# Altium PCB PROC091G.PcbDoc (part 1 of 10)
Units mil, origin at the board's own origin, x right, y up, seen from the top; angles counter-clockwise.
Board outline 4538.11 x 994.94 mil, 8 copper layers (Top Layer, GND1, Sig1, PWR1, PWR2, Sig2, GND2, Bottom Layer), stack 59.155 mil thick; 446 components, 329 nets, 5050 pads, 868 vias.
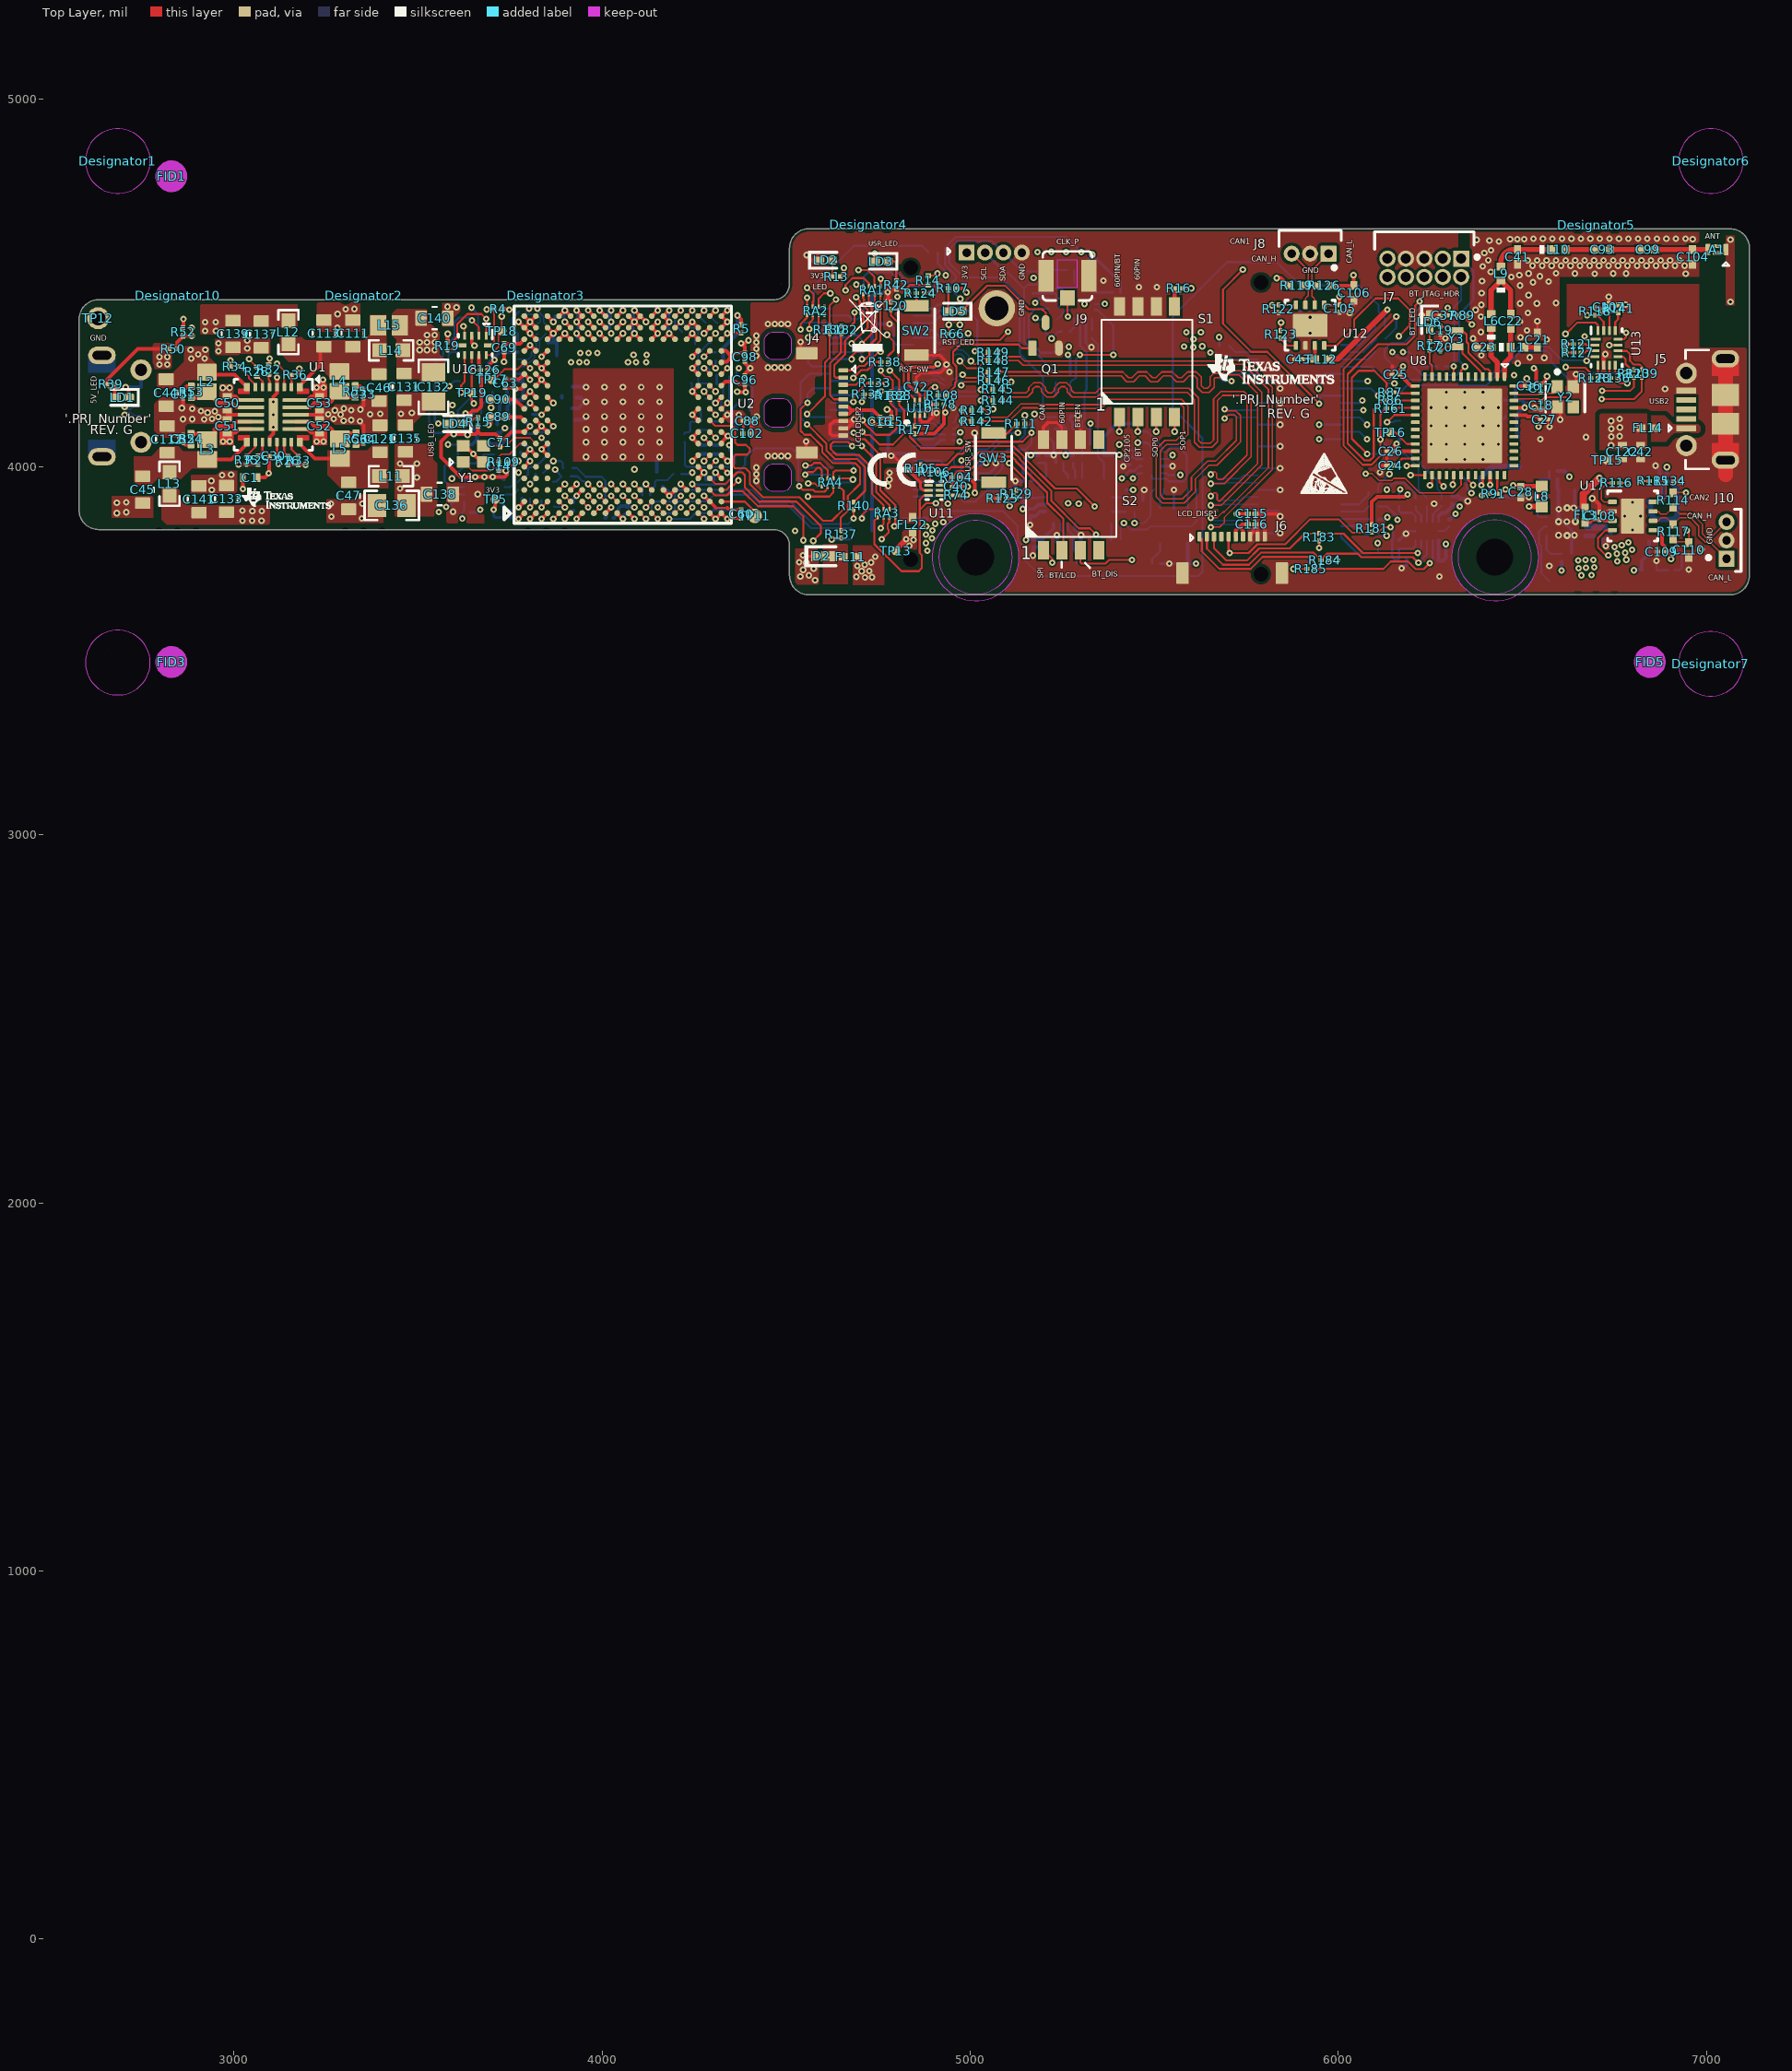
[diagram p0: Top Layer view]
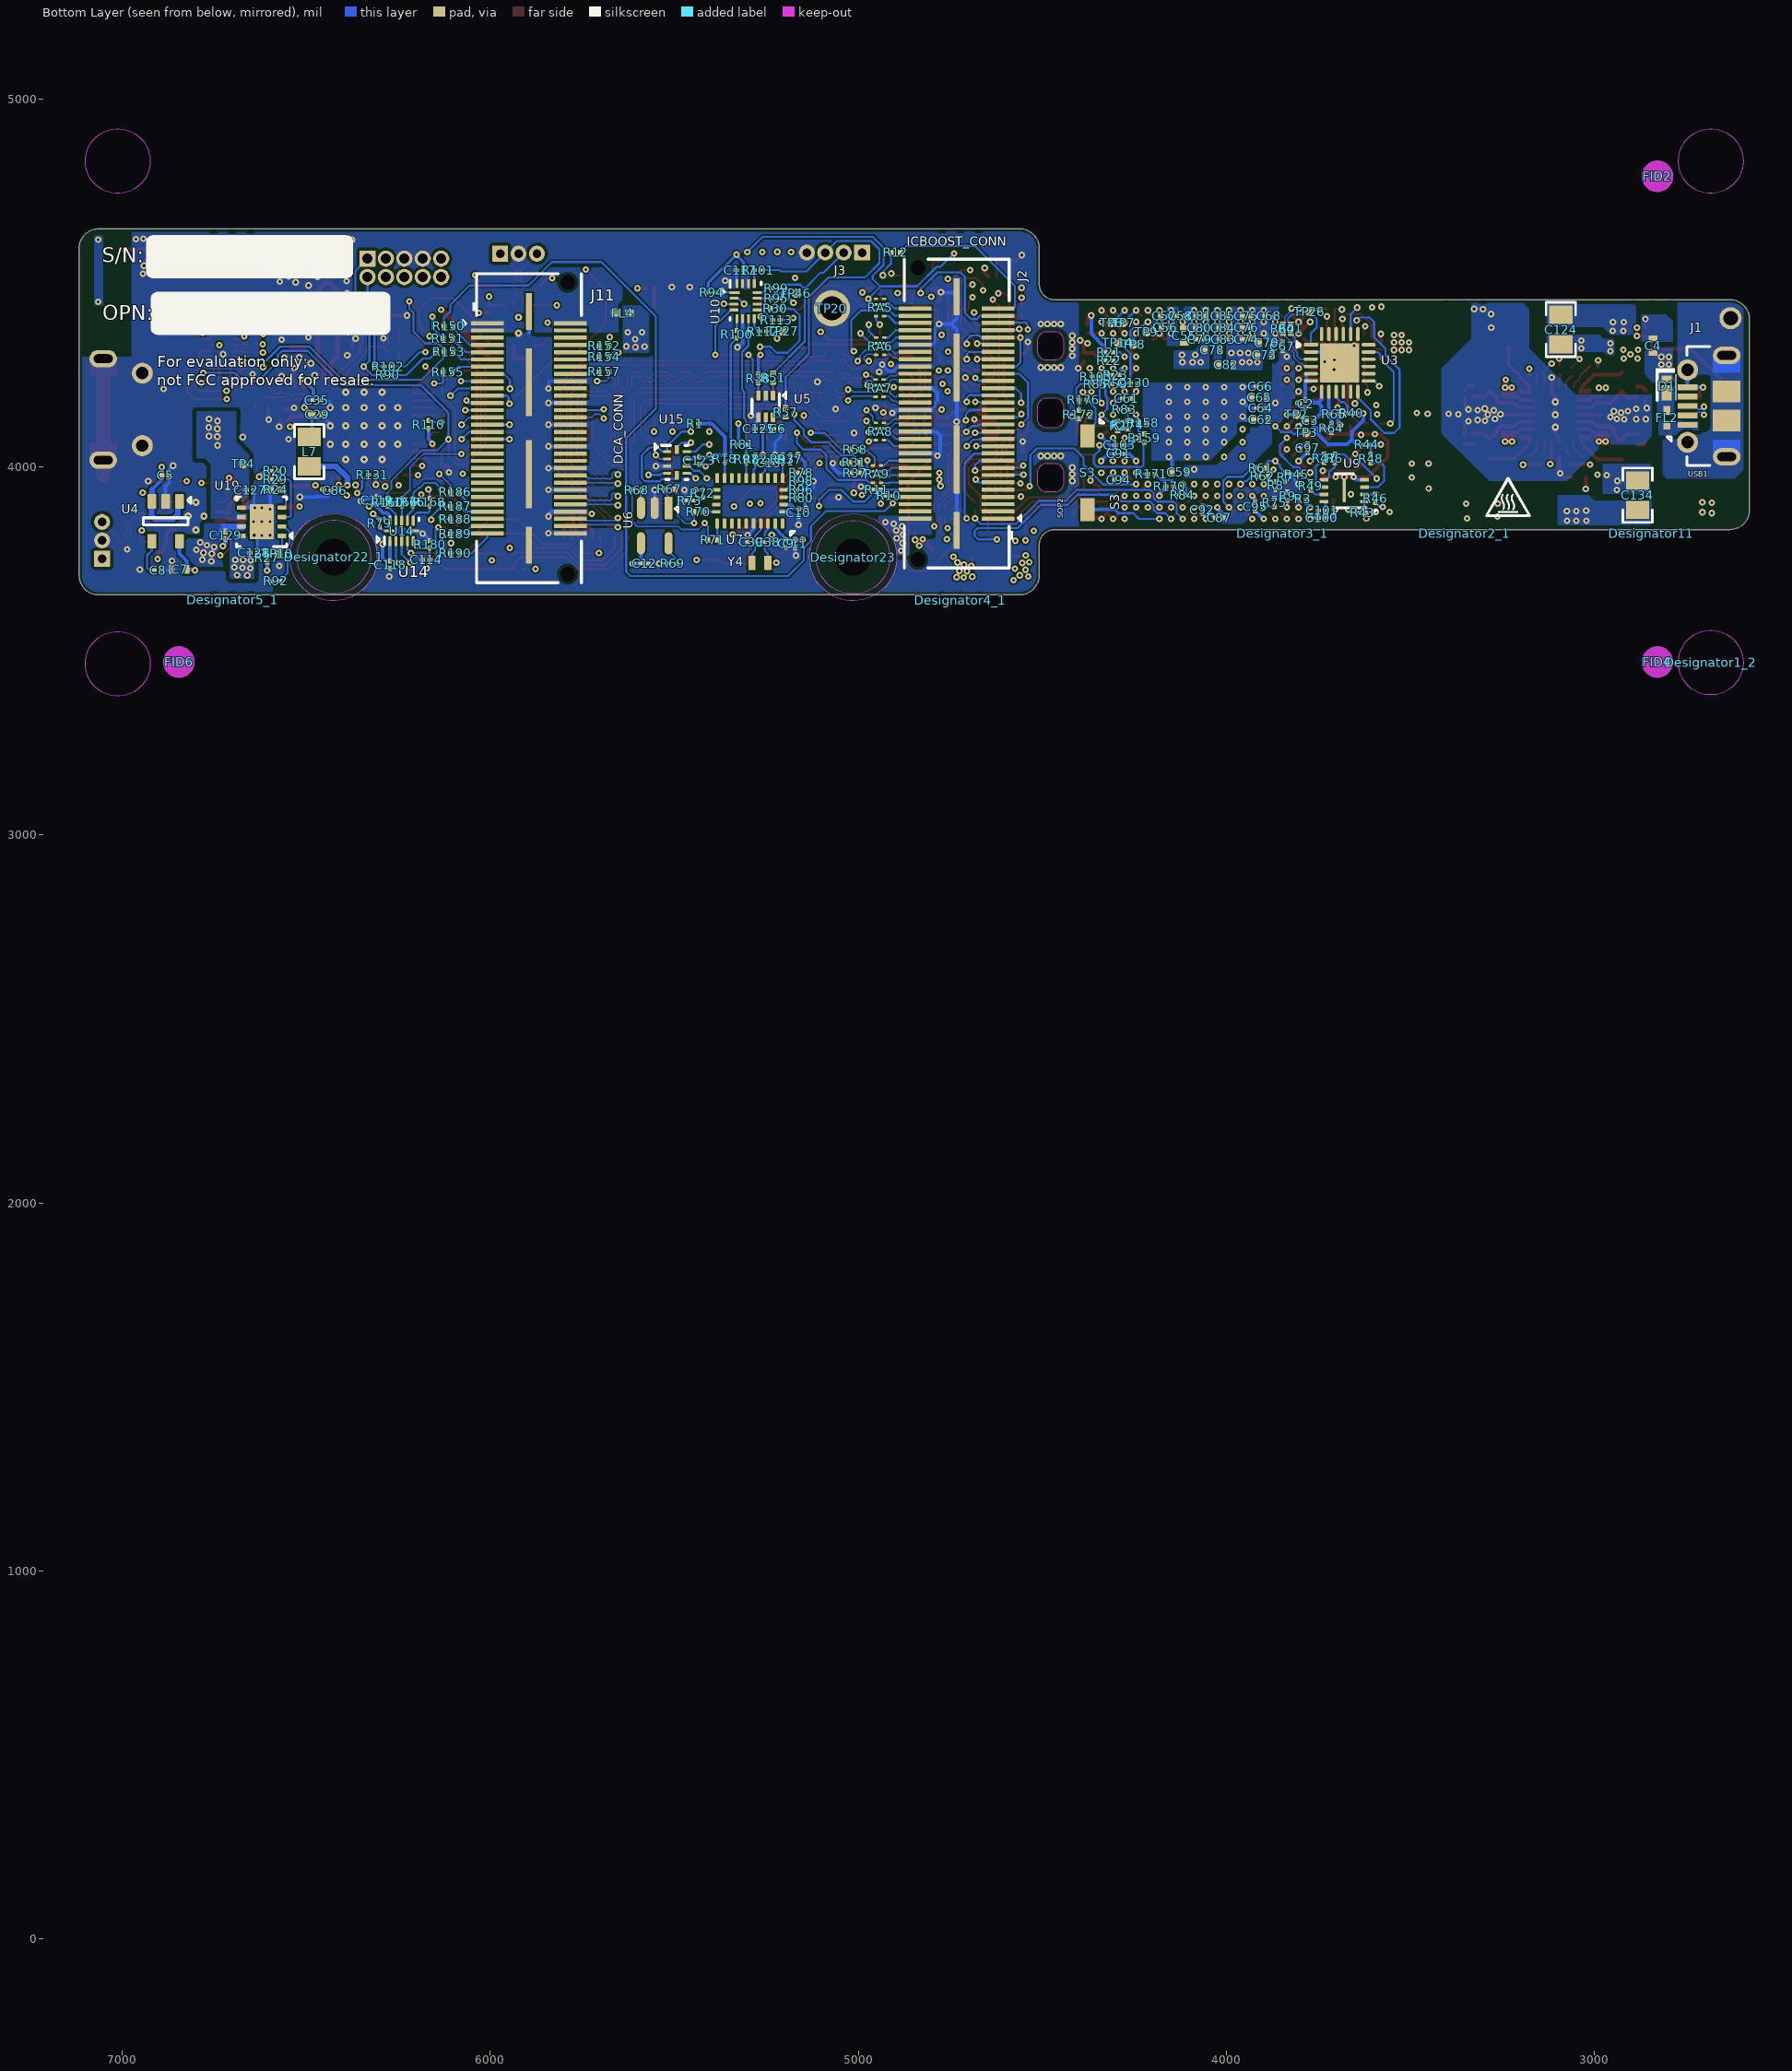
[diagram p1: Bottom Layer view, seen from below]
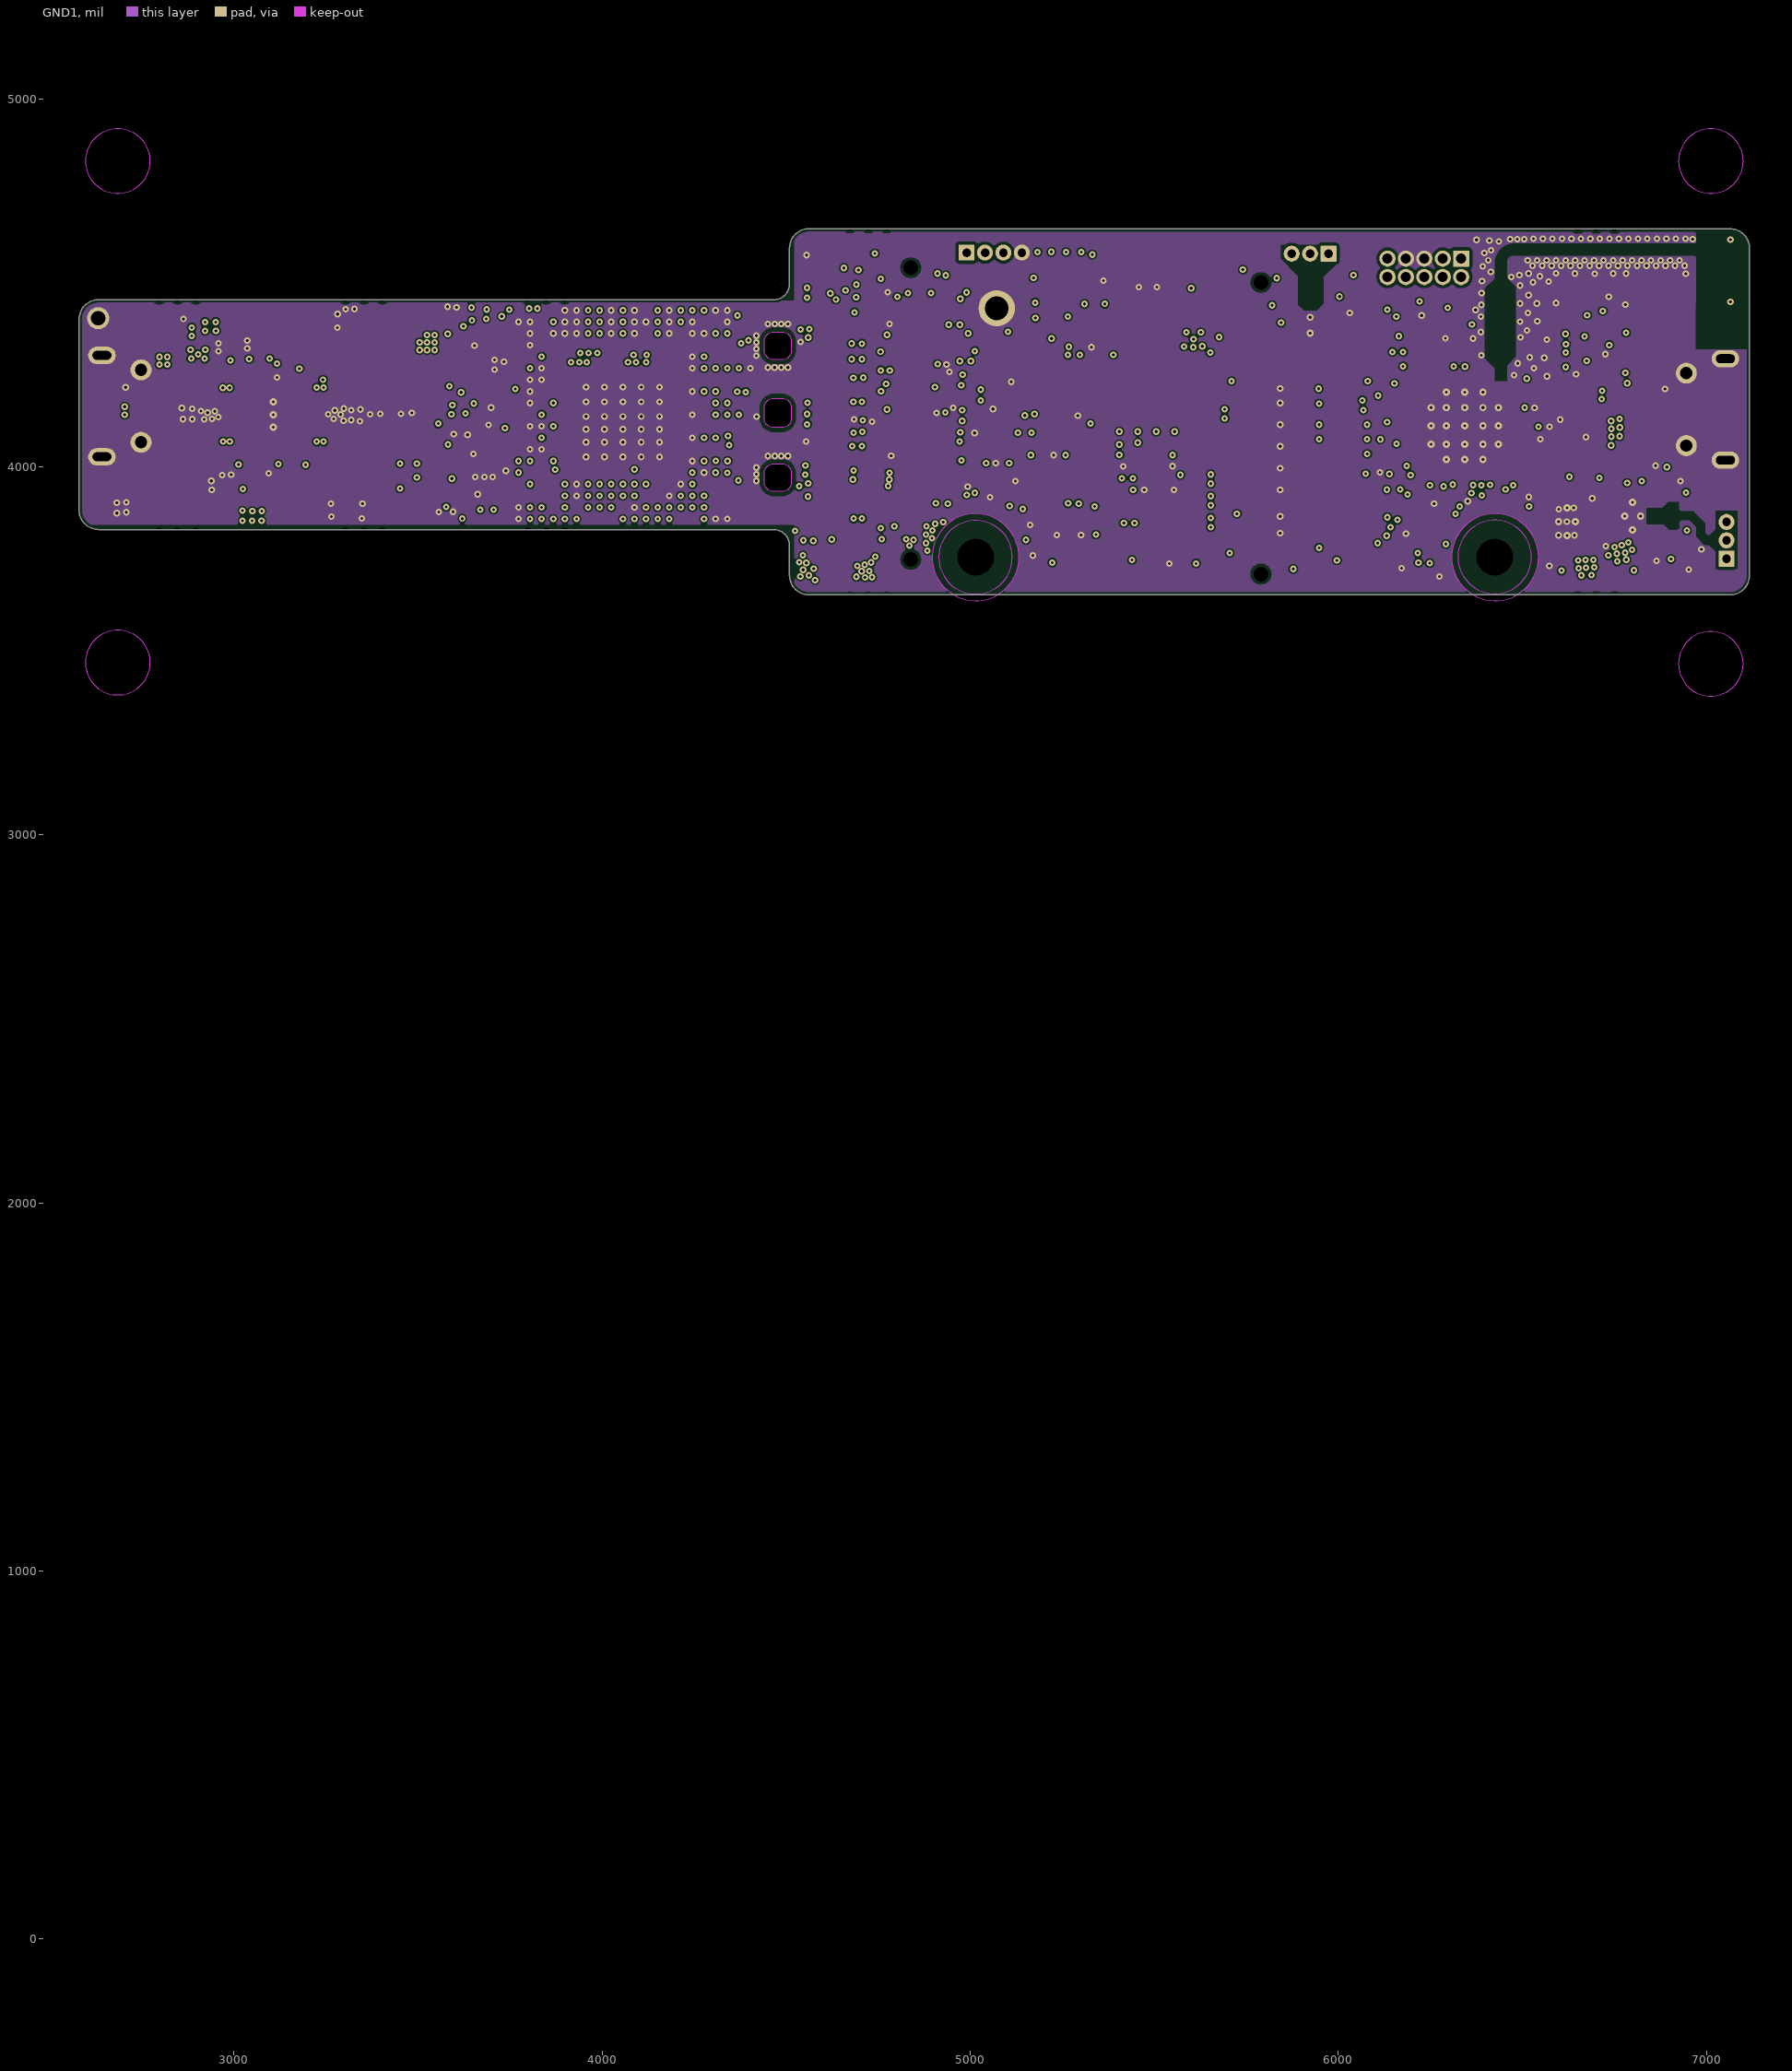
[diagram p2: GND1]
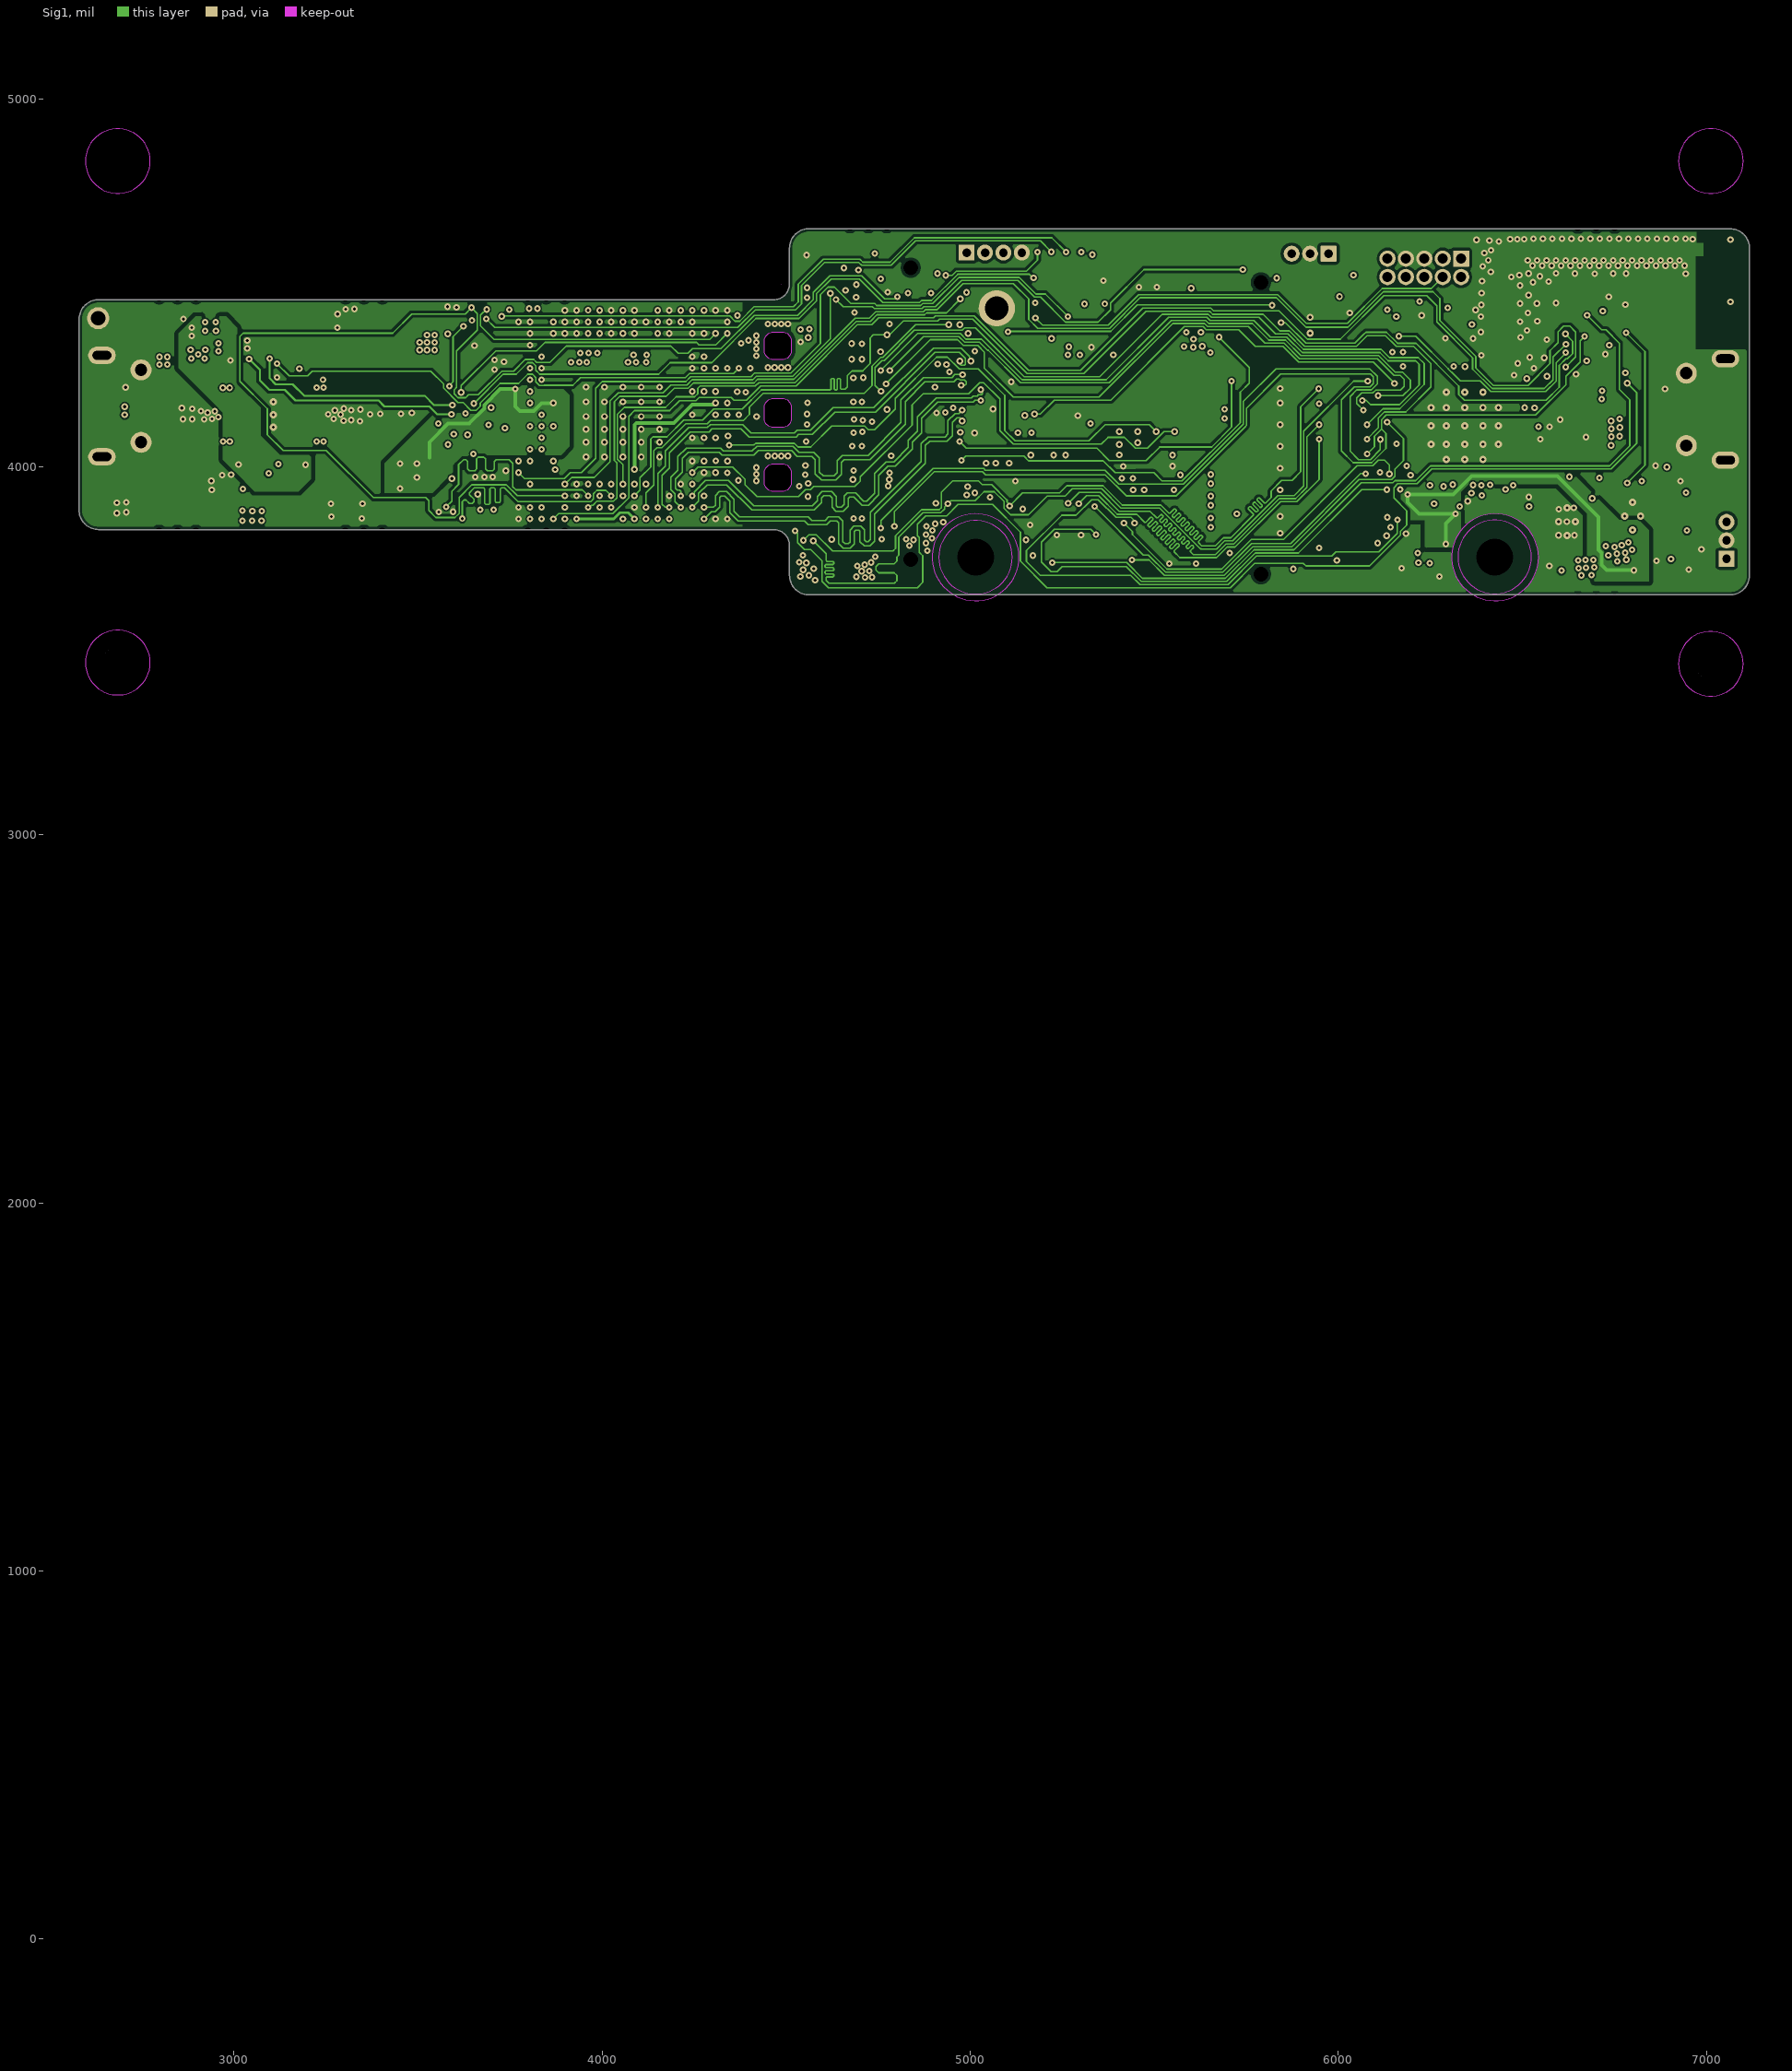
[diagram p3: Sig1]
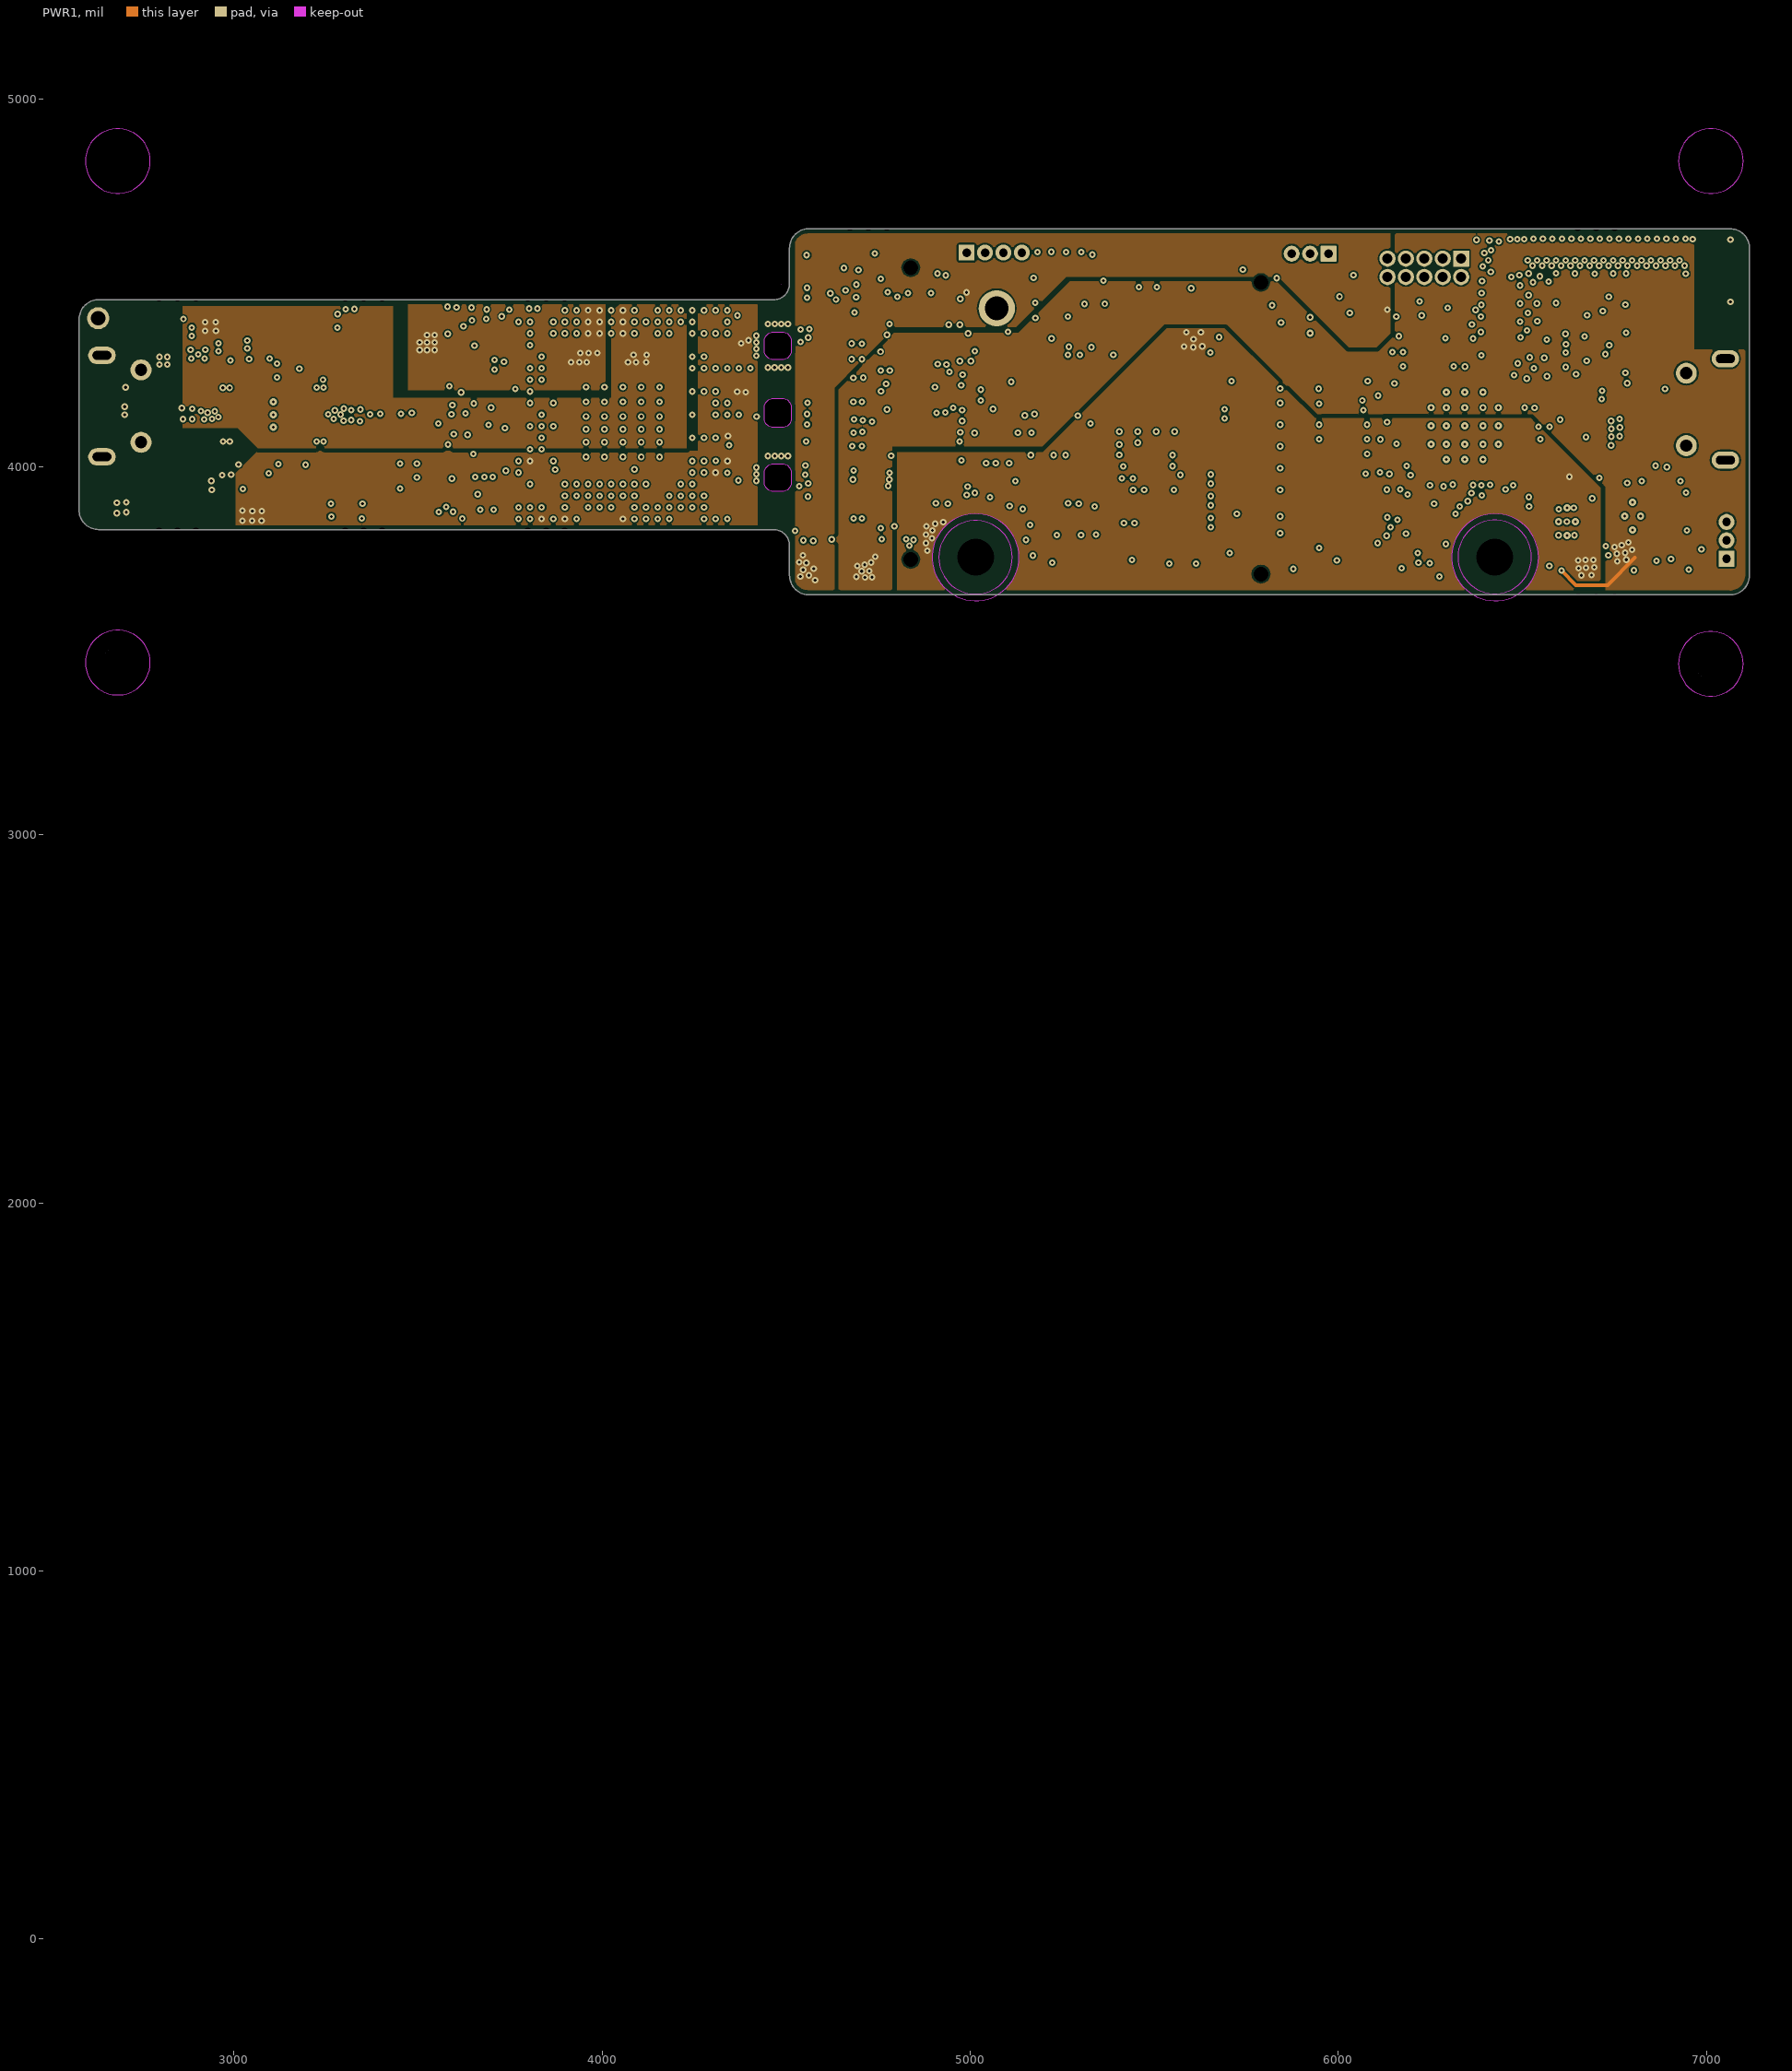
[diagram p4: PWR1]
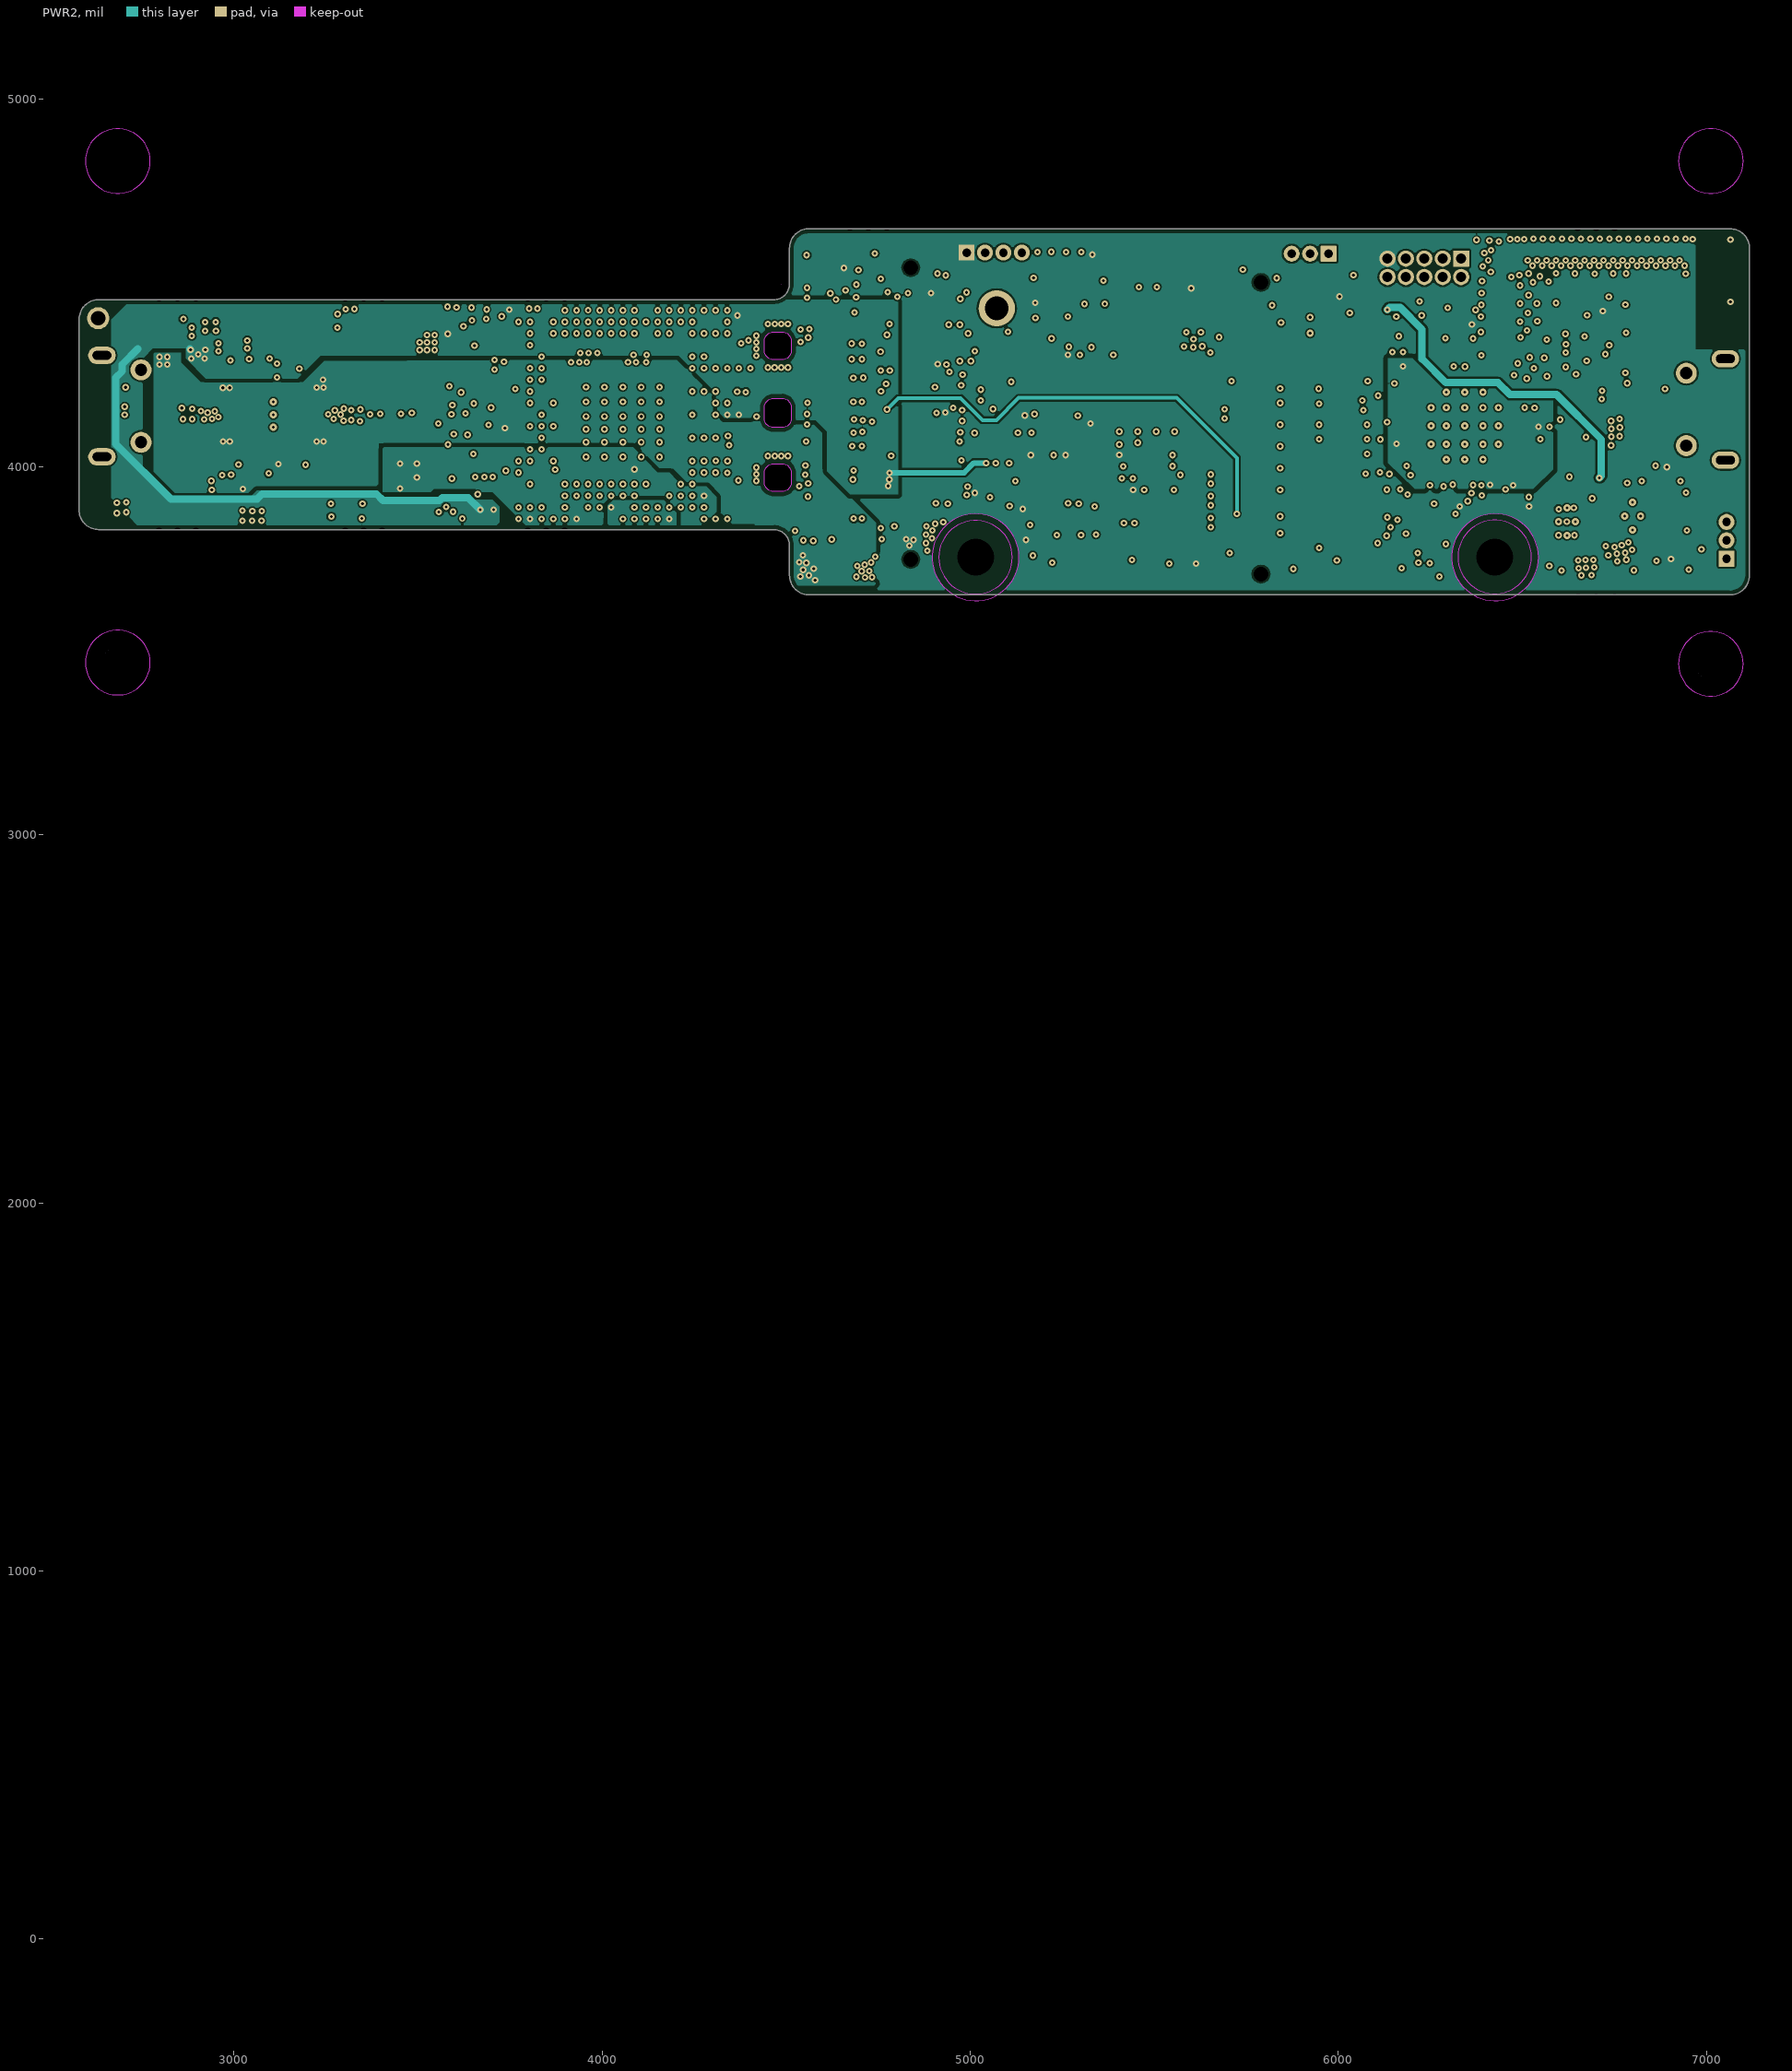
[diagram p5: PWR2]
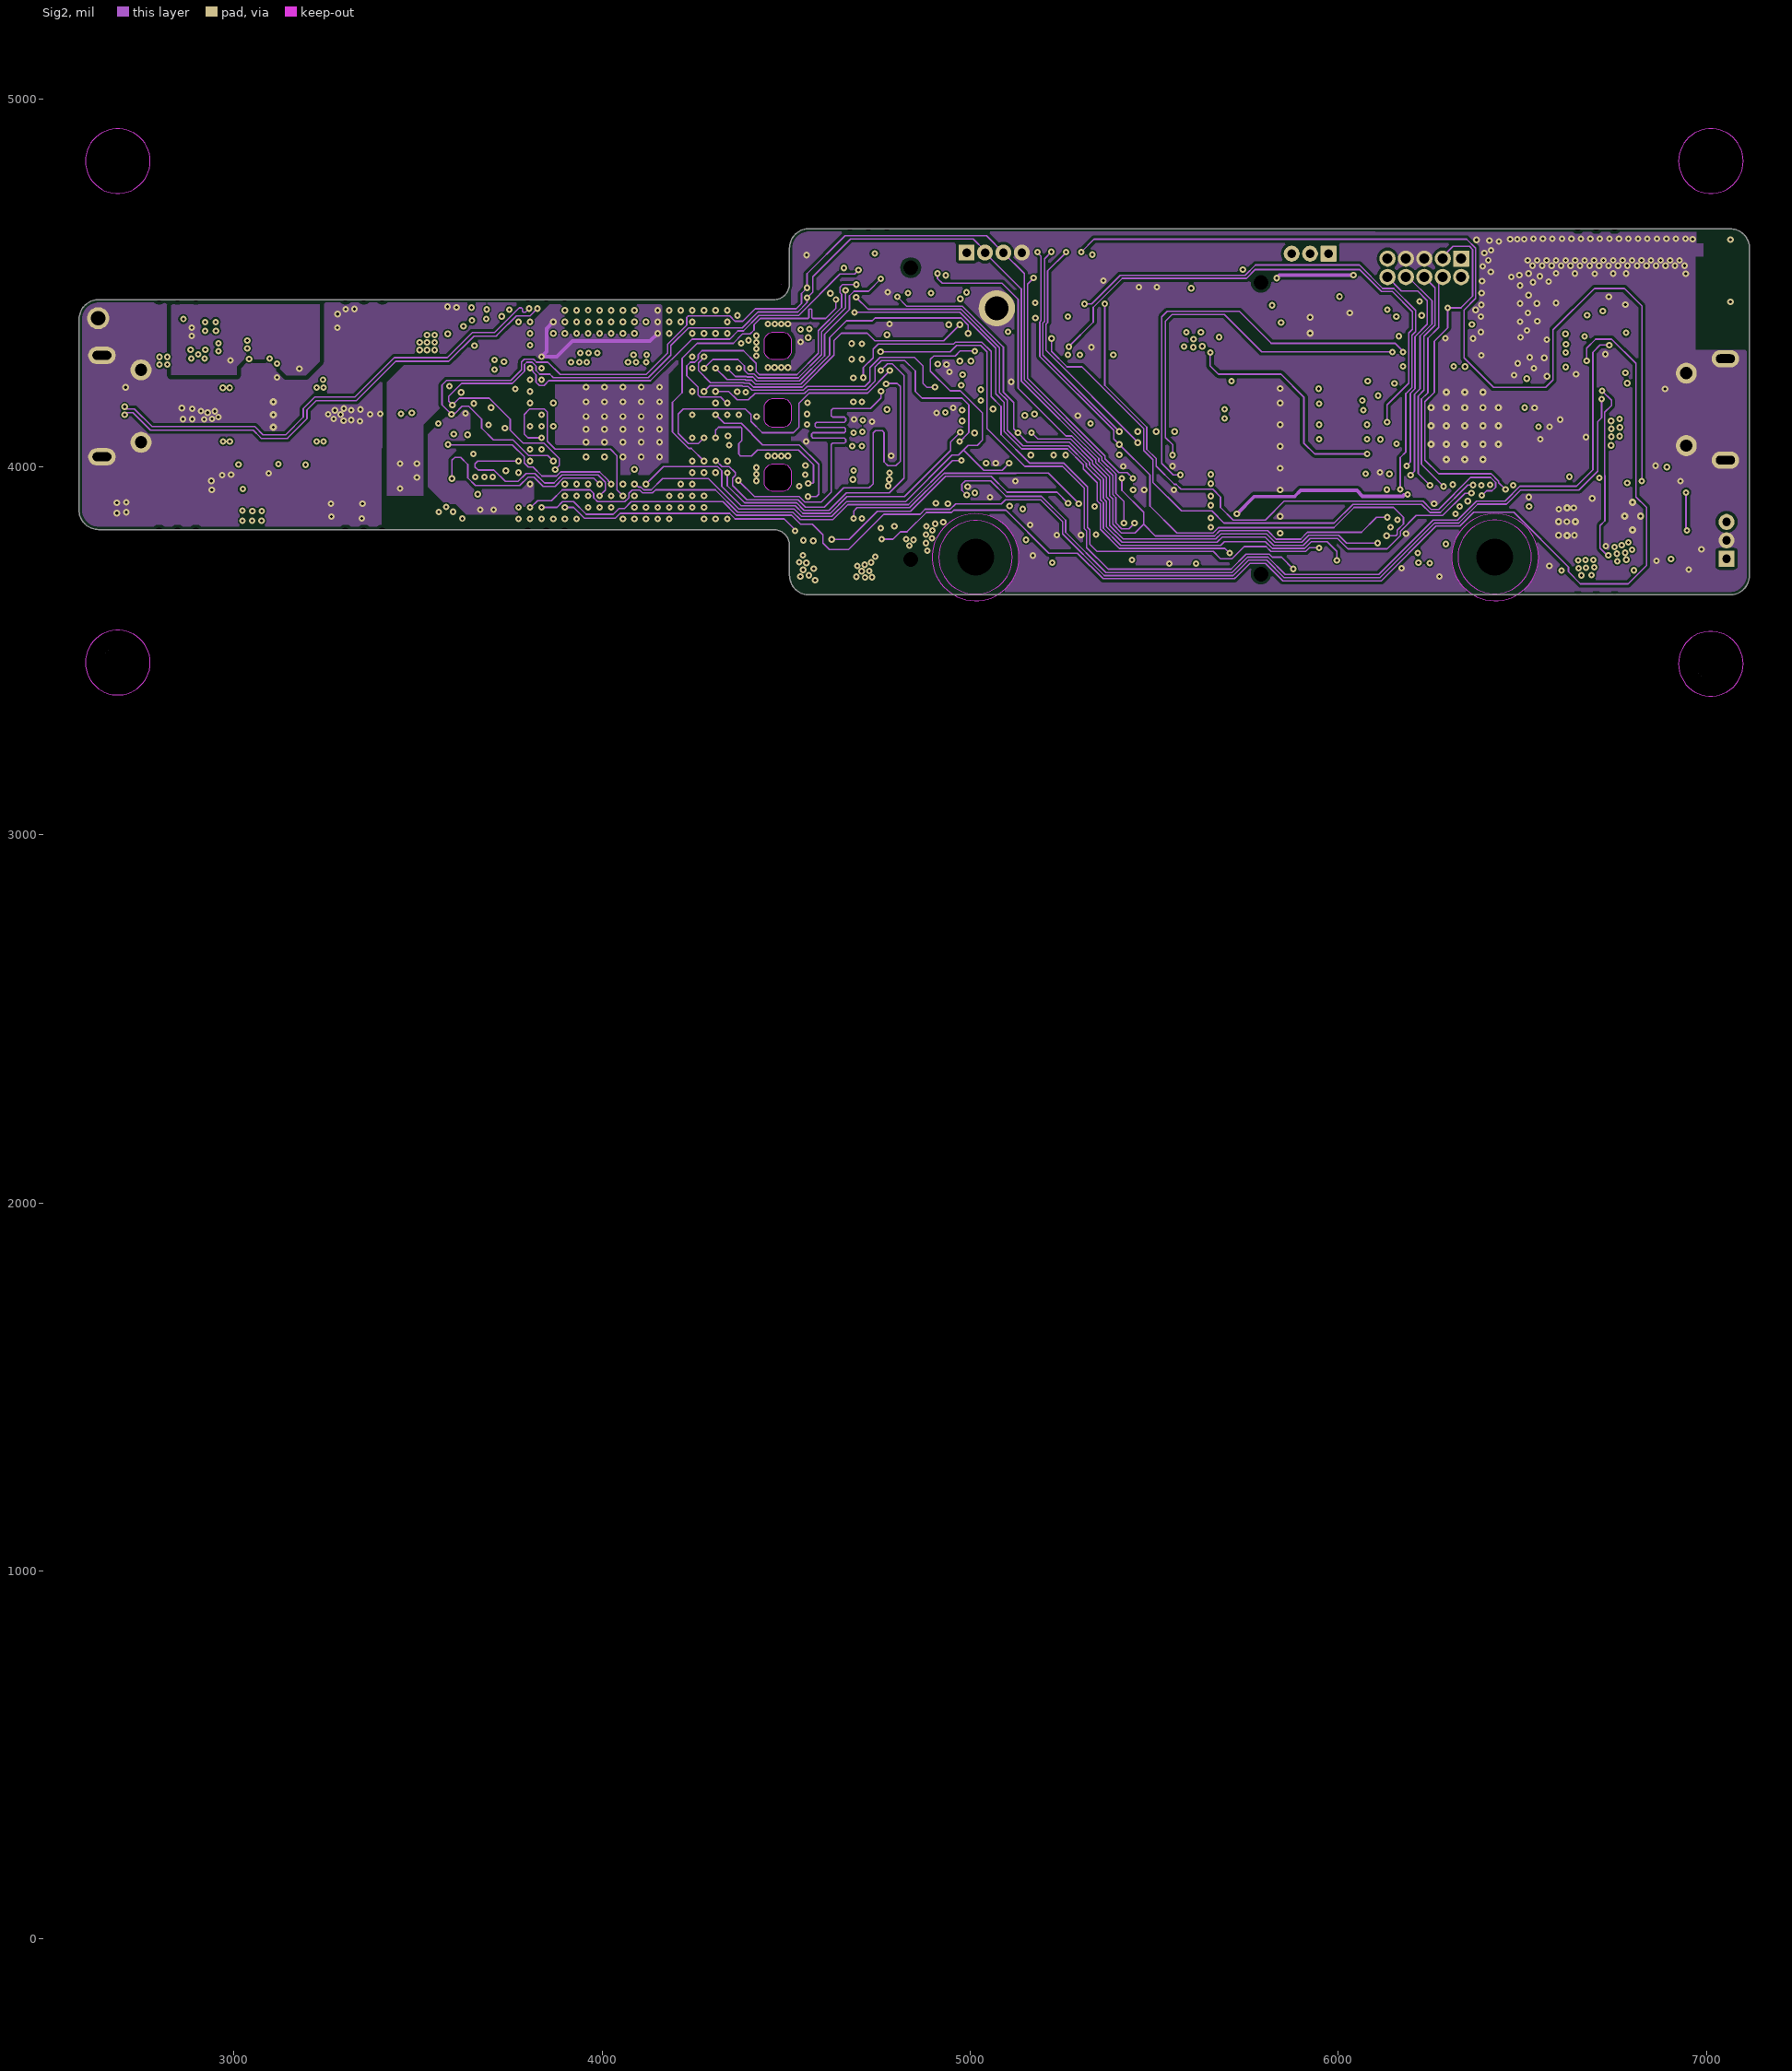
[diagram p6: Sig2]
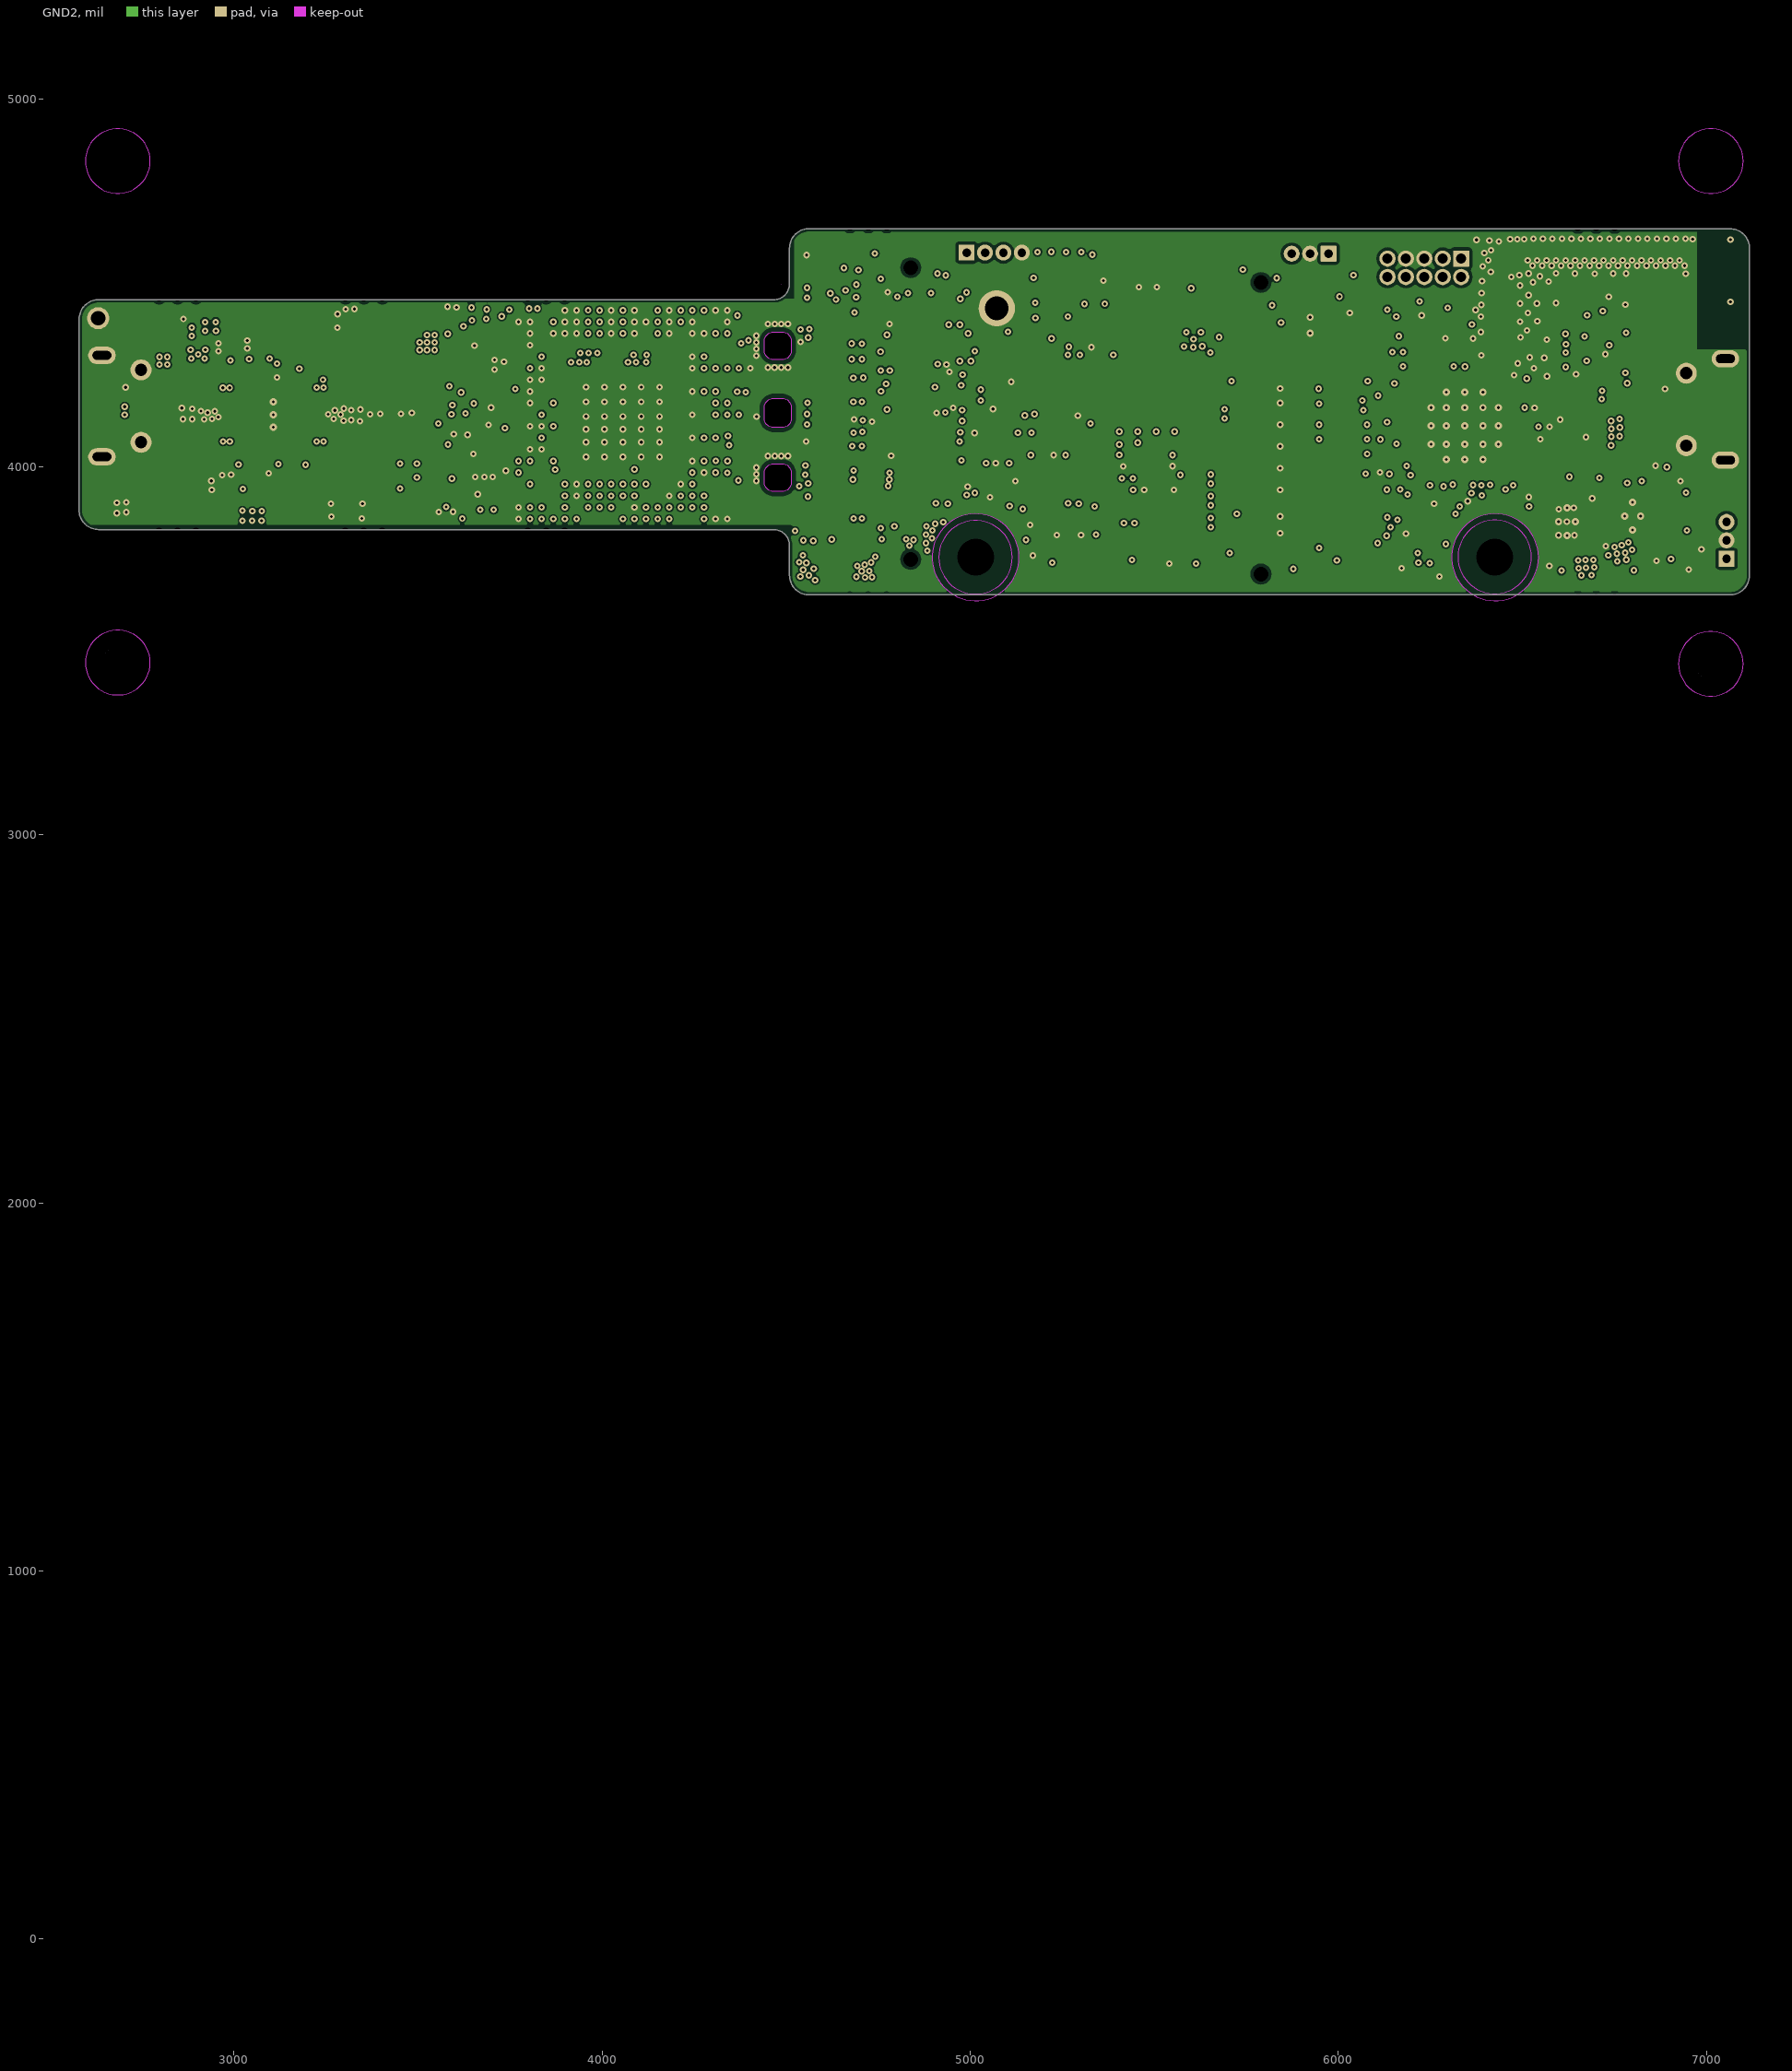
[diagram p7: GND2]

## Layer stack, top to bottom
Top Solder: solder mask 2, Solder Resist, Dk 4.4
Top Layer: signal copper 1.85
Dielectric1: core 1.462, FR-4 High Tg, Dk 3.832
Dielectric 2: core 2.224, FR-4 High Tg, Dk 3.832
GND1: signal copper 2.638
Dielectric3: dielectric 4, FR-4 High Tg, Dk 4.4
Sig1: signal copper 1.26
Dielectric4: dielectric 3.162, FR-4 High Tg, Dk 4.13
Dielectric 5: dielectric 3.162, FR-4 High Tg, Dk 4.13
Dielectric 6: dielectric 3.162, FR-4 High Tg, Dk 4.13
PWR1: signal copper 2.638
Dielectric7: dielectric 8, FR-4 High Tg, Dk 4.41
PWR2: signal copper 2.638
Dielectric8: dielectric 3.175, FR-4 High Tg, Dk 4.13
Dielectric 9: dielectric 3.175, FR-4 High Tg, Dk 4.13
Dielectric 10: dielectric 3.175, FR-4 High Tg, Dk 4.13
Sig2: signal copper 1.26
Dielectric11: dielectric 4, FR-4 High Tg, Dk 4.4
GND2: signal copper 2.638
Dielectric12: dielectric 2.224, FR-4 High Tg, Dk 3.832
Dielectric 13: dielectric 1.462, FR-4 High Tg, Dk 3.832
Bottom Layer: signal copper 1.85
Bottom Solder: solder mask 2, Solder Resist, Dk 4.4

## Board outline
2632.27,3829.45 2632.34,3829.45 4466.14,3829.45 cw(c4466.14,3786.46) 4509.12,3786.46 4509.12,3705.09 ccw(c4562.14,3705.09) 4562.14,3652.08 ccw(c4562.14,3657.09) 4562.83,3652.13 7062.33,3652.13 ccw(c7064.08,3656.83) 7064.08,3651.81 ccw(c7064.08,3704.83) 7117.07,3703.16 ccw(c7112.34,3704.83) 7117.35,3704.83 7117.35,4593.25 ccw(c7112.34,4593.47) 7117.36,4593.47 ccw(c7064.34,4593.47) 7064.34,4646.49 ccw(c7064.34,4641.47) 7063.39,4646.4 4562.79,4646.71 ccw(c4562.15,4641.74) 4562.15,4646.75 ccw(c4562.15,4593.74) 4509.14,4593.74 4509.14,4496.76 4509.13,4496.76 cw(c4514.15,4496.76) 4509.14,4496.84 4509.13,4496.76 cw(c4466.15,4496.76) 4466.15,4453.77 2634.33,4453.77 ccw(c2632.58,4449.07) 2632.58,4454.09 ccw(c2632.58,4401.07) 2579.56,4401.07 ccw(c2584.58,4401.07) 2579.57,4400.91 ccw(c2584.58,4400.76) 2579.56,4400.76 2579.56,3884.21 ccw(c2584.27,3882.46) 2579.25,3882.46 ccw(c2632.27,3882.46)
cut-out: 4466.37,4365.95 4494.11,4365.95 4503.29,4362.14 4510.33,4355.11 4514.13,4345.92 4514.13,4340.95 4514.13,4311.32 4510.33,4302.14 4503.29,4295.1 4494.11,4291.3 4489.13,4291.3 4461.39,4291.3 4452.2,4295.1 4445.17,4302.14 4441.37,4311.32 4441.37,4316.3 4441.37,4345.92 4445.17,4355.11 4452.2,4362.14 4461.39,4365.95 4466.37,4365.95
cut-out: 4489.13,4185.46 4494.1,4185.46 4503.29,4181.66 4510.32,4174.62 4514.13,4165.44 4514.13,4160.46 4514.13,4131.32 4514.13,4126.35 4510.32,4117.16 4503.29,4110.12 4494.1,4106.32 4489.13,4106.32 4466.36,4106.32 4461.39,4106.32 4452.2,4110.12 4445.17,4117.16 4441.36,4126.35 4441.36,4131.32 4441.36,4160.46 4441.36,4165.44 4445.17,4174.62 4452.2,4181.66 4461.39,4185.46 4489.13,4185.46
cut-out: 4466.36,4007.54 4494.1,4007.54 4503.28,4003.73 4510.32,3996.7 4514.12,3987.51 4514.12,3982.54 4514.12,3957.89 4514.12,3952.91 4510.32,3943.73 4503.28,3936.69 4494.1,3932.89 4489.12,3932.89 4461.38,3932.89 4452.19,3936.69 4445.16,3943.73 4441.36,3952.91 4441.36,3957.89 4441.36,3982.54 4441.36,3987.51 4445.16,3996.7 4452.19,4003.73 4461.38,4007.54 4466.36,4007.54
cut-out: 4477.74,4007.54
cut-out: 4486.41,4495.33

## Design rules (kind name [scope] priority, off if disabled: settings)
AcuteAngle [All] p1: minimum=4.50000000000000E+0001 checktracksonly=TRUE
AssemblyTestPointUsage [All] p1: valid=2
BoardOutlineClearance BoardOutlineClearance_1 [InNet('GND')] p1: gap=8 ignorepadtopadclearanceinfootprint=FALSE
BoardOutlineClearance [All and (Not (OnLayer('Bottom Overlay') or OnLayer('Top Overlay') or InComponentClass('Fid')))] p2: gap=12 ignorepadtopadclearanceinfootprint=FALSE except(0: Text-OutlineEdge; 10: Via-OutlineEdge)
Clearance Keepout [(OnLayer('Keep-Out Layer'))] p1: gap=0.01 ignorepadtopadclearanceinfootprint=FALSE except(5.9: THPad-THPad; 7: Arc-THPad Track-THPad THPad-Via; 8: THPad-Fill THPad-Poly THPad-Region)
Clearance RF_TRACE [InNetClass('RF')] p2: gap=4 ignorepadtopadclearanceinfootprint=FALSE except(0: Arc-Hole Track-Hole SMDPad-Hole THPad-Hole Via-Hole Fill-Hole Poly-Hole Region-Hole Text-Hole; 2: Arc-Text Track-Text SMDPad-Text THPad-Text Via-Text Fill-Text Poly-Text Region-Text Text-Text; 5.9: THPad-THPad; 6: SMDPad-Fill SMDPad-Poly SMDPad-Region Via-Fill Via-Poly Via-Region; 7: Arc-THPad Track-THPad THPad-Via; 8: THPad-Fill THPad-Poly THPad-Region; 8.92: Arc-Fill Arc-Poly Arc-Region Track-Fill Track-Poly Track-Region; 15: Fill-Fill Fill-Poly Fill-Region Poly-Poly Poly-Region Region-Region)
Clearance AOP_T-B [WithinRoom('BGA') vs (OnLayer('Bottom Layer') or OnLayer('Top Layer'))] p3: gap=4 ignorepadtopadclearanceinfootprint=TRUE except(0: Arc-Hole Track-Hole SMDPad-Hole THPad-Hole Via-Hole Fill-Hole Poly-Hole Region-Hole Text-Hole; 3.8: SMDPad-Via; 3.9: Arc-Via Track-Via; 5.9: THPad-THPad; 7: Arc-THPad Track-THPad THPad-Via; 8: THPad-Fill THPad-Poly THPad-Region Fill-Fill Fill-Poly Fill-Region Poly-Poly Poly-Region Region-Region)
Clearance AOP_Sig [WithinRoom('BGA') vs (OnLayer('sig1') or OnLayer('sig2'))] p4: gap=4 ignorepadtopadclearanceinfootprint=FALSE except(0: Arc-Hole Track-Hole SMDPad-Hole THPad-Hole Via-Hole Fill-Hole Poly-Hole Region-Hole Text-Hole; 3.5: Arc-Arc Arc-Track Arc-Via Arc-Text Track-Track Track-Via Track-Text SMDPad-Text THPad-Text Via-Via Via-Text Fill-Text Poly-Text Region-Text Text-Text; 3.8: SMDPad-Via; 5.9: THPad-THPad; 7: Arc-THPad Track-THPad THPad-Via; 8: SMDPad-THPad THPad-Fill THPad-Poly THPad-Region; 15: Fill-Fill Fill-Poly Fill-Region Poly-Poly Poly-Region Region-Region)
Clearance 50E_INNERlayer [(OnLayer('sig1') or OnLayer('Sig2'))] p5: gap=4.2 ignorepadtopadclearanceinfootprint=TRUE except(0: Arc-Hole Track-Hole SMDPad-Hole THPad-Hole Via-Hole Fill-Hole Poly-Hole Region-Hole Text-Hole; 2: SMDPad-Text Fill-Text Poly-Text Region-Text Text-Text; 3.5: Arc-Via Track-Via; 5.9: THPad-THPad; 6: SMDPad-Fill SMDPad-Poly SMDPad-Region; 7: Arc-THPad Track-THPad THPad-Via; 8: Arc-Fill Arc-Poly Arc-Region Track-Fill Track-Poly Track-Region THPad-Fill THPad-Poly THPad-Region; 12: Fill-Fill Fill-Poly Fill-Region Poly-Poly Poly-Region Region-Region)
Clearance INNERlayer [(OnLayer('pwr1') or OnLayer('pwr2'))] p6: gap=8 ignorepadtopadclearanceinfootprint=TRUE except(0: Arc-Hole Track-Hole SMDPad-Hole THPad-Hole Via-Hole Fill-Hole Poly-Hole Region-Hole Text-Hole; 2: SMDPad-Text Fill-Text Poly-Text Region-Text Text-Text; 4: Via-Fill Via-Poly Via-Region; 4.2: Arc-Text Track-Text THPad-Text Via-Via Via-Text; 5: THPad-Fill THPad-Poly THPad-Region; 5.9: THPad-THPad; 6: Arc-Via Arc-Fill Arc-Poly Arc-Region Track-Via Track-Fill Track-Poly Track-Region; 7: THPad-Via; 12: Fill-Fill Fill-Poly Fill-Region Poly-Poly Poly-Region Region-Region)
Clearance 100E [InDifferentialPairClass('100E') vs (OnLayer('Sig1') or OnLayer('Sig2'))] p7: gap=8 ignorepadtopadclearanceinfootprint=FALSE except(0: Arc-Hole Track-Hole SMDPad-Hole THPad-Hole Via-Hole Fill-Hole Poly-Hole Region-Hole Text-Hole; 2: Arc-Text Track-Text THPad-Text Via-Text Fill-Text Poly-Text Region-Text Text-Text; 4: Arc-SMDPad Track-SMDPad SMDPad-SMDPad SMDPad-THPad SMDPad-Via SMDPad-Text Via-Fill Via-Poly Via-Region; 5: Arc-Via Track-Via; 5.9: THPad-THPad; 6: SMDPad-Fill SMDPad-Poly SMDPad-Region Fill-Fill Fill-Poly Fill-Region Poly-Poly Poly-Region Region-Region; 7: Arc-THPad Track-THPad THPad-Via; 16: Arc-Arc Arc-Track Track-Track)
Clearance 100E_1 [InDifferentialPairClass('100E') vs (OnLayer('Bottom Layer') or OnLayer('Top Layer'))] p8: gap=8 ignorepadtopadclearanceinfootprint=FALSE except(0: Arc-Hole Track-Hole SMDPad-Hole THPad-Hole Via-Hole Fill-Hole Poly-Hole Region-Hole Text-Hole; 2: Arc-Text Track-Text THPad-Text Via-Text Fill-Text Poly-Text Region-Text Text-Text; 4: Arc-SMDPad Track-SMDPad SMDPad-SMDPad SMDPad-THPad SMDPad-Via SMDPad-Text Via-Fill Via-Poly Via-Region; 5: Arc-Via Track-Via; 5.9: THPad-THPad; 6: SMDPad-Fill SMDPad-Poly SMDPad-Region Fill-Fill Fill-Poly Fill-Region Poly-Poly Poly-Region Region-Region; 7: Arc-THPad Track-THPad THPad-Via; 11: Arc-Arc Arc-Track Track-Track)
Clearance 90E_OUTSIDE [InDifferentialPairClass('90E') vs OnOutside] p9: gap=6 ignorepadtopadclearanceinfootprint=TRUE except(0: Arc-Hole Track-Hole SMDPad-Hole THPad-Hole Via-Hole Fill-Fill Fill-Poly Fill-Region Fill-Hole Poly-Poly Poly-Region Poly-Hole Region-Region Region-Hole Text-Hole; 2: Arc-Text Track-Text SMDPad-Text THPad-Text Via-Text Fill-Text Poly-Text Region-Text Text-Text; 3.8: SMDPad-Via; 4: Arc-SMDPad Track-SMDPad SMDPad-SMDPad Via-Via Via-Fill Via-Poly Via-Region; 4.5: Arc-Arc Arc-Track Arc-Via Track-Track Track-Via; 5.9: THPad-THPad; 7: Arc-THPad Track-THPad SMDPad-THPad THPad-Via; 8: THPad-Fill THPad-Poly THPad-Region)
Clearance [All] p10: gap=1 ignorepadtopadclearanceinfootprint=TRUE except(0: Arc-Hole Track-Hole SMDPad-Hole THPad-Hole Via-Hole Fill-Hole Poly-Hole Region-Hole Text-Hole; 3.8: SMDPad-Via; 3.9: Arc-Via Track-Via; 4: Arc-SMDPad Track-SMDPad SMDPad-SMDPad Via-Via Via-Fill Via-Poly Via-Region; 4.5: Arc-Arc Arc-Track Track-Track; 5: Arc-Fill Arc-Poly Arc-Region Track-Fill Track-Poly Track-Region; 5.9: THPad-THPad; 6: SMDPad-Fill SMDPad-Poly SMDPad-Region; 7: Arc-THPad Track-THPad SMDPad-THPad THPad-Via; 8: THPad-Fill THPad-Poly THPad-Region; 12: Fill-Fill Fill-Poly Fill-Region Poly-Poly Poly-Region Region-Region)
Clearance "SAME NET" [All] p11: gap=0 ignorepadtopadclearanceinfootprint=FALSE except(0.5: SMDPad-Text; 5.9: THPad-THPad)
ComponentClearance ComponentClearance_R199_187 [InComponent('J11') or InComponent('TP20')] p1: gap=-1 collisioncheckmode=3 verticalgap=10 showdistances=FALSE
ComponentClearance ComponentClearance_R188_204 [InComponent('R188') vs InComponent('R204')] p2: gap=-1 collisioncheckmode=3 verticalgap=10 showdistances=FALSE
ComponentClearance [All] p3: gap=1 collisioncheckmode=3 verticalgap=10 showdistances=FALSE
ComponentClearance ComponentClearance_MountingHoles_FiducialMarks [InComponentClass('Mounting Holes') vs InComponentClass('FiducialMark')] p4: gap=50 collisioncheckmode=3 verticalgap=10 showdistances=FALSE
ComponentClearance ComponentClearance_Shunt [InComponentClass('Header') vs InComponentClass('Shunt')] p5: gap=1 collisioncheckmode=3 verticalgap=0 showdistances=FALSE
ComponentClearance ComponentClearance_Logo [InComponentClass('Logo')] p6: gap=50 collisioncheckmode=3 verticalgap=10 showdistances=FALSE
ComponentClearance ComponentClearance_ScrewToNut [(HasFootprint('NY PMS 440 0025 PH')) vs (HasFootprint('Keystone_1902C'))] p7: gap=5 collisioncheckmode=3 verticalgap=10 showdistances=FALSE
ComponentClearance ComponentClearance_MountingHoles [InComponentClass('Mounting Holes')] p8: gap=20 collisioncheckmode=3 verticalgap=100000 showdistances=FALSE
ComponentClearance ComponentClearance_SmallPassives [HasFootprint('0201*') or HasFootprint('0402*') or HasFootprint('0508') or HasFootprint('0603*') or HasFootprint('0612') or HasFootprint('0805*') or HasFootprint('0815*') or HasFootprint('0830*') or HasFootprint('1206*') or HasFootprint('1210*') or HasFootprint('1808*') or HasFootprint('1812*') or HasFootprint('1825*') or HasFootprint('2010*') or HasFootprint('2220*') or HasFootprint('2225*') or HasFootprint('2512*') or HasFootprint('2728*') or HasFootprint('3518*') vs HasFootprint('0201*') or HasFootprint('0402*') or HasFootprint('0508') or HasFootprint('0603*') or HasFootprint('0612') or HasFootprint('0805*') or HasFootprint('0815*') or HasFootprint('0830*') or HasFootprint('1206*') or HasFootprint('1210*') or HasFootprint('1808*') or HasFootprint('1812*') or HasFootprint('1825*') or HasFootprint('2010*') or HasFootprint('2220*') or HasFootprint('2225*') or HasFootprint('2512*') or HasFootprint('2728*') or HasFootprint('3518*')] p9: gap=10 collisioncheckmode=3 verticalgap=10 showdistances=FALSE
ComponentClearance ComponentClearance_THtoSMT [IsThruComponent vs IsSMTComponent] p10: gap=5 collisioncheckmode=3 verticalgap=20 showdistances=FALSE
ComponentClearance ComponentClearance_THtoTH [IsThruComponent vs IsThruComponent] p11: gap=20 collisioncheckmode=3 verticalgap=30 showdistances=FALSE
DiffPairsRouting Diff_100E [InDifferentialPairClass('100E')] p1: maxlimit=10 minlimit=7 mostfreqgap=10 toplayer_maxgap=7 toplayer_prefgap=7 toplayer_minwidth=4 toplayer_maxwidth=4 toplayer_prefwidth=4 midlayer1_mingap=10 midlayer1_minwidth=15 midlayer1_maxwidth=15 midlayer1_prefwidth=15 midlayer2_mingap=8 midlayer2_maxgap=8 midlayer2_prefgap=8 midlayer2_minwidth=3.5 midlayer2_maxwidth=3.5 midlayer2_prefwidth=3.5 midlayer3_mingap=10 midlayer3_minwidth=15 midlayer3_maxwidth=15 midlayer3_prefwidth=15 midlayer6_mingap=10 midlayer6_minwidth=15 midlayer6_maxwidth=15 midlayer6_prefwidth=15 midlayer7_mingap=8 midlayer7_maxgap=8 midlayer7_prefgap=8 midlayer7_minwidth=3.5 midlayer7_maxwidth=3.5 midlayer7_prefwidth=3.5 midlayer8_mingap=10 midlayer8_minwidth=15 midlayer8_maxwidth=15 midlayer8_prefwidth=15 bottomlayer_maxgap=7 bottomlayer_prefgap=7 bottomlayer_minwidth=4 bottomlayer_maxwidth=4 bottomlayer_prefwidth=4 maxuncoupledlength=500
DiffPairsRouting Diff_90E [InDifferentialPairClass('90E')] p2: maxlimit=100 minlimit=4.5 mostfreqgap=10 toplayer_maxgap=4.5 toplayer_prefgap=4.5 toplayer_minwidth=4 toplayer_maxwidth=4 toplayer_prefwidth=4 midlayer1_mingap=10 midlayer1_minwidth=15 midlayer1_maxwidth=15 midlayer1_prefwidth=15 midlayer2_mingap=6 midlayer2_maxgap=6 midlayer2_prefgap=6 midlayer2_minwidth=4 midlayer2_maxwidth=4 midlayer2_prefwidth=4 midlayer3_mingap=10 midlayer3_minwidth=15 midlayer3_maxwidth=15 midlayer3_prefwidth=15 midlayer6_mingap=10 midlayer6_minwidth=15 midlayer6_maxwidth=15 midlayer6_prefwidth=15 midlayer7_mingap=6 midlayer7_maxgap=6 midlayer7_prefgap=6 midlayer7_minwidth=4 midlayer7_maxwidth=4 midlayer7_prefwidth=4 midlayer8_mingap=10 midlayer8_minwidth=15 midlayer8_maxwidth=15 midlayer8_prefwidth=15 bottomlayer_maxgap=4.5 bottomlayer_prefgap=4.5 bottomlayer_minwidth=4 bottomlayer_maxwidth=4 bottomlayer_prefwidth=4 maxuncoupledlength=1000
DiffPairsRouting Diff_120E [InDifferentialPairClass('120E')] p3: maxlimit=10 minlimit=6.1 mostfreqgap=10 toplayer_maxgap=6.1 toplayer_prefgap=6.1 toplayer_minwidth=4 toplayer_maxwidth=4 toplayer_prefwidth=4 midlayer1_mingap=10 midlayer1_minwidth=15 midlayer1_maxwidth=15 midlayer1_prefwidth=15 midlayer2_mingap=10 midlayer2_minwidth=15 midlayer2_maxwidth=15 midlayer2_prefwidth=15 midlayer3_mingap=10 midlayer3_minwidth=15 midlayer3_maxwidth=15 midlayer3_prefwidth=15 midlayer6_mingap=10 midlayer6_minwidth=15 midlayer6_maxwidth=15 midlayer6_prefwidth=15 midlayer7_mingap=10 midlayer7_minwidth=15 midlayer7_maxwidth=15 midlayer7_prefwidth=15 midlayer8_mingap=10 midlayer8_minwidth=15 midlayer8_maxwidth=15 midlayer8_prefwidth=15 bottomlayer_maxgap=6.1 bottomlayer_prefgap=6.1 bottomlayer_minwidth=4 bottomlayer_maxwidth=4 bottomlayer_prefwidth=4 maxuncoupledlength=500
FabricationTestPointUsage TestPointUsage [All] p1: valid=2 allowmultiple=FALSE
FabricationTestpoint Testpoint [All] p1: side=3 testpointundercomponent=TRUE minsize=40 maxsize=100 preferedsize=60 minholesize=0 maxholesize=40 preferedholesize=32 testpointgrid=1 allowsidetop=TRUE allowsidebottom=TRUE usegrid=TRUE gridtolerance=0.01
FanoutControl Fanout_LCC [IsLCC] p1: bgadir=Out bgaviamode=Centered fanoutstyle=Auto fanoutdirection=Alternating viagrid=1 // Fanout_LCC (Default Rule)
FanoutControl Fanout_BGA [IsBGA] p2: bgadir=Out bgaviamode=Centered fanoutstyle=Auto fanoutdirection=Alternating viagrid=1 // Fanout_BGA (Default Rule)
FanoutControl Fanout_Default [All] p4: bgadir=Out bgaviamode=Centered fanoutstyle=Auto fanoutdirection=Alternating viagrid=1 // Fanout_Default (Default Rule)
FanoutControl Fanout_Small [(CompPinCount < 5)] p5: bgadir=Out bgaviamode=Centered fanoutstyle=Auto fanoutdirection=OutThenIn viagrid=1 // Fanout_Small (Default Rule)
HoleSize [All] p1: absolutevalues=TRUE maxlimit=251 minlimit=5.9 maxpercent=80.000 minpercent=20.000
MatchedLengths [InNetClass('LVDS_IC')] p1: tolerance=20 checknetsindiffpair=FALSE checkdiffpairvsdiffpair=TRUE checkxsignals=TRUE checkothers=TRUE
MatchedLengths USB [InxSignalClass('USB')] p2: tolerance=5 checknetsindiffpair=TRUE checkdiffpairvsdiffpair=FALSE checkxsignals=FALSE checkothers=FALSE
MatchedLengths QSPI [InxSignalClass('QSPI')] p3: tolerance=100 checknetsindiffpair=FALSE checkdiffpairvsdiffpair=TRUE checkxsignals=TRUE checkothers=TRUE
MatchedLengths SPI [InxSignalClass('SPI & HOSTINT')] p4: tolerance=200 checknetsindiffpair=FALSE checkdiffpairvsdiffpair=TRUE checkxsignals=TRUE checkothers=TRUE
MatchedLengths JTAG [InxSignalClass('JTAG')] p5: tolerance=100 checknetsindiffpair=FALSE checkdiffpairvsdiffpair=TRUE checkxsignals=TRUE checkothers=TRUE
MinimumAnnularRing MinimumAnnularRing_ThermalPadVias [IsVia and InAnyComponent] p1: minimumring=3
MinimumAnnularRing [All] p2: minimumring=3
MinimumSolderMaskSliver [All] p1: minsoldermaskwidth=2.5
PlaneConnect [All] p1: planeconnectstyle=Direct reliefexpansion=10 reliefentries=4 reliefconductorwidth=10 reliefairgap=10
PolygonConnect [All] p1: connectstyle=Direct reliefconductorwidth=10 reliefentries=4 polygonreliefangle="90 Angle" airgapwidth=10
RoomDefinition PROC091G_Hardware [InComponentClass('PROC091G_Hardware')] p1: confinementstyle=ConfineIn formatcopy=TRUE lockcomponents=FALSE outline 3757.84,4447.61 4382.71,4447.61 4382.71,3834 3757,3834
RoutingVias [All] p1: holewidth=8 width=18 viastyle="Through Hole" minholewidth=7.87 minwidth=17 maxholewidth=40 maxwidth=30
RoutingVias ThermalPadVias [IsVia and InAnyComponent] p2: holewidth=7.87 width=19.68 viastyle="Through Hole" minholewidth=7.87 minwidth=19.68 maxholewidth=12.99 maxwidth=23.62
SilkToBoardRegionClearance [Not ((IsComment or IsDesignator) And (Hide <> 'False')) and not InRegion(1000,500,4000,800)] p1:
SilkToSilkClearance [All] p1: silktosilkclearance=0
SilkToSolderMaskClearance SilkToComponentPadClearance [(IsPad or IsFill or IsRegion) and InAnycomponent] p1: minsilkscreentomaskgap=3 clearancetoexposedcopper=TRUE
SilkToSolderMaskClearance "Silk to Solder Mask Opening" [All] p2: minsilkscreentomaskgap=3 clearancetoexposedcopper=FALSE
SolderMaskExpansion [All] p1: expansion=1.97
Width RF [InNetClass('RF')] p1: maxlimit=100 minlimit=5.5 preferedwidth=10 toplayer_prefwidth=14.15 midlayer1_minwidth=10 midlayer1_maxwidth=10 midlayer2_minwidth=10 midlayer2_maxwidth=10 midlayer3_minwidth=10 midlayer3_maxwidth=10 midlayer6_minwidth=10 midlayer6_maxwidth=10 midlayer7_minwidth=10 midlayer7_maxwidth=10 midlayer8_minwidth=10 midlayer8_maxwidth=10 bottomlayer_minwidth=10 bottomlayer_maxwidth=10 minimp=50.000000 maximp=50.000000 favimp=50.000000
Width [All] p2: maxlimit=100 minlimit=4 preferedwidth=6 toplayer_maxwidth=40 toplayer_prefwidth=5.5 midlayer1_minwidth=4.2 midlayer1_maxwidth=20 midlayer1_prefwidth=4.2 midlayer2_minwidth=4.2 midlayer2_maxwidth=10 midlayer2_prefwidth=4.2 midlayer7_minwidth=4.2 midlayer7_maxwidth=20 midlayer7_prefwidth=4.2 midlayer8_minwidth=6 midlayer8_prefwidth=10 bottomlayer_maxwidth=40 bottomlayer_prefwidth=5.5 minimp=50.000000 maximp=50.000000 favimp=50.000000
15 further rules are at their usual default settings.

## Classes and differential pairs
component class PROC091G_Hardware: Designator22_1 Designator23 FID1 FID2 FID3 FID4 FID5 FID6 ZZ1 ZZ2 ZZ3 ZZ4 ZZ5.1 ZZ5.2
differential pair class 120E: NewDifferentialPair1 NewDifferentialPair2
differential pair class 100E: AR_LVDS_0 AR_LVDS_0_R AR_LVDS_1 AR_LVDS_1_R AR_LVDS_CLK AR_LVDS_CLK_R AR_LVDS_FRCLK AR_LVDS_FRCLK_R
differential pair class 90E: USB
component class PROC091G_RST_GPIOs_I2C: C6 C9 C10 C11 C12 C13 C38 C39 C72 C120 C125 J3 LD2 LD3 LD5 Q1 R13 R18 R38 R42 R51 R57 R67 R68 R69 R70 R71 R72 R73 R77 R78 R80 R81 R82 R93 R96 R97 R98 R107 R108 R111 R124 R125 R129 R177 R178 SW2 SW3 TP15 TP20 U5 U6 U7 U16 Y4
component class PROC091G_PMIC: C30 C31 C32 C33 C34 C44 C45 C46 C47 C50 C51 C52 C53 C111 C112 C113 C121 C124 C131 C132 C133 C134 C135 C136 C137 C138 C139 C140 C141 L2 L3 L4 L5 L11 L12 L13 L14 L15 LD1 R25 R26 R28 R31 R32 R33 R34 R35 R36 R37 R39 R50 R52 R53 R54 R55 R56 TP5 TP12 U1
component class PROC091G_HD_CONN_PWR_SW: C127 C128 C129 D2 FL4 FL11 FL22 J2 J11 R10 R11 R12 R14 R20 R24 R27 R29 R58 R88 R92 R130 R132 R133 R135 R137 R138 R140 R142 R143 R144 R145 R146 R147 R148 R149 R150 R151 R152 R153 R154 R155 R157 R186 R187 R188 R189 R190 RA1 RA2 RA3 RA4 RA5 RA6 RA7 RA8 RA9 TP10 TP13 U19
component class PROC091G_FLASH_USB_TO_UART: C1 C2 C3 C4 C100 C101 C126 D1 FL2 J1 LD4 R6 R15 R19 R40 R41 R43 R44 R45 R46 R47 R48 R49 R60 R64 R65 TP18 TP19 TP26 U3 U9 U18
component class PROC091G_CAN_INTERFACE: C40 C43 C105 C106 C107 C108 C109 C110 FL3 FL12 J8 J10 R66 R74 R104 R105 R106 R114 R115 R116 R117 R118 R119 R120 R121 R122 R123 R126 R127 R128 R134 R136 R139 R141 U11 U12 U13 U17
component class PROC091G_BT_DISPLAY: A1 C5 C7 C8 C15 C16 C17 C18 C19 C20 C21 C22 C23 C24 C25 C26 C27 C28 C29 C35 C36 C37 C41 C86 C93 C99 C104 C114 C115 C116 C117 C118 C119 J4 J6 J7 L1 L6 L7 L8 L9 L10 LD6 R17 R30 R76 R79 R86 R87 R89 R90 R91 R94 R95 R99 R100 R101 R102 R110 R112 R113 R131 R160 R161 R166 R168 R180 R181 R182 R183 R184 R185 TP16 TP27 TP46 U4 U8 U10 U14 Y2 Y3
component class PROC091G_AOP_PWR: C55 C56 C57 C58 C59 C60 C61 C62 C63 C64 C65 C66 C67 C68 C69 C70 C73 C74 C75 C76 C78 C79 C80 C81 C82 C83 C84 C85 C87 C88 C89 C90 C91 C92 C94 C95 C96 C97 C98 C102 C103 TP11
component class PROC091G_AOP_IO: C14 C71 C130 J9 R2 R3 R4 R5 R7 R8 R9 R21 R22 R23 R59 R61 R62 R75 R83 R84 R85 R103 R109 R158 R159 R170 R171 R172 R174 R176 S3 TP2 TP3 TP6 TP7 TP8 TP9 TP14 TP17 U2 Y1
component class PROC091G_ANALOG_MUX: C42 C122 C123 FL14 J5 R1 R16 S1 S2 TP4 U15
component class FiducialMark: FID1 FID2 FID3 FID4 FID5 FID6
component class AssemblyNote: ZZ1 ZZ2 ZZ3 ZZ4 ZZ5.1 ZZ5.2
differential pair NewDifferentialPair1: +NetJ8_1 -NetJ8_3
differential pair USB: +USB_DP -USB_DM
differential pair NewDifferentialPair2: +NetJ10_1 -NetJ10_3
differential pair AR_LVDS_CLK: +AR_LVDS_CLK_P -AR_LVDS_CLK_N
differential pair AR_LVDS_FRCLK: +AR_LVDS_FRCLK_P -AR_LVDS_FRCLK_N
differential pair AR_LVDS_1: +AR_LVDS_1_P -AR_LVDS_1_N
differential pair AR_LVDS_0: +AR_LVDS_0_P -AR_LVDS_0_N
differential pair AR_LVDS_0_R: +NetJ11_56 -NetJ11_58
differential pair AR_LVDS_1_R: +NetJ11_50 -NetJ11_52
differential pair AR_LVDS_CLK_R: +NetJ11_44 -NetJ11_46
differential pair AR_LVDS_FRCLK_R: +NetJ11_26 -NetJ11_28

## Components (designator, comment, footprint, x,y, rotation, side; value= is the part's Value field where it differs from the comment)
A1 "ANT016008LCS2442MA2" FP-ANT016008LCS2442MA2_SMT_ANT-0 7028.91,4589.83 r180 top
C1 "CL05A106MP5NUNC" 0402_070 3044.3,3970.8 r180 top value=10uF
C2 "GRM033R6YA104KE14D" "FP-GRM033R6YA104KE14D_0201 (0603 Metric)-IPC_C" 3785.88,4170.74 r90 bottom
C3 "GRM033R6YA104KE14D" "FP-GRM033R6YA104KE14D_0201 (0603 Metric)-IPC_C" 3772.95,4125.72 r180 bottom
C4 "CL05A106MP5NUNC" 0402_070 2841.59,4328.91 r90 bottom value=10uF
C5 "CL03A105MO3NRNH" FP-CL03A105MO3NRNH_0201-IPC_C 6882.81,3977 r180 bottom
C6 "GRM033R6YA104KE14D" "FP-GRM033R6YA104KE14D_0201 (0603 Metric)-IPC_C" 5221.01,4103.02 r0 bottom locked
C7 "CL05A106MP5NUNC" 0402_070 6844.78,3720.79 r0 bottom value=10uF
C8 "CL03A103KA3NNNC" FP-CL03A103KA3NNNC_0201-IPC_C 6903.19,3719.01 r180 bottom
C9 "GRM033R6YA104KE14D" "FP-GRM033R6YA104KE14D_0201 (0603 Metric)-IPC_C" 5197.1,3791.56 r90 bottom locked
C10 "GRM033R6YA104KE14D" "FP-GRM033R6YA104KE14D_0201 (0603 Metric)-IPC_C" 5162.69,3875.17 r90 bottom
C11 "CL03A105MO3NRNH" FP-CL03A105MO3NRNH_0201-IPC_C 5172.1,3791.41 r270 bottom
C12 "GRM033R6YA104KE14D" "FP-GRM033R6YA104KE14D_0201 (0603 Metric)-IPC_C" 5580.92,3737.11 r0 bottom
C13 "GRM033R6YA104KE14D" "FP-GRM033R6YA104KE14D_0201 (0603 Metric)-IPC_C" 5242.93,4010.48 r0 bottom
C14 "GRM0335C1H4R7BA01D" 0201_033L 3719.34,4001.36 r90 top value=4.7pF
C15 "CL03A105MO3NRNH" FP-CL03A105MO3NRNH_0201-IPC_C 4785.89,4123.62 r270 top
C16 "CL03A105MO3NRNH" FP-CL03A105MO3NRNH_0201-IPC_C 4755.82,4123.62 r270 top
C17 "GRM0335C1H8R0BA01D" "FP-GRM0335C1H8R0BA01D_0201 (0603 metric)-IPC_C" 6550.62,4212.94 r90 top
C18 "GRM0335C1H8R0BA01D" "FP-GRM0335C1H8R0BA01D_0201 (0603 metric)-IPC_C" 6550.62,4166.75 r270 top
C19 "250R05L120JV4T" FP-250R05L120JV4T_0201-IPC_C 6277.6,4370.87 r270 top
C20 "250R05L120JV4T" FP-250R05L120JV4T_0201-IPC_C 6277.6,4324.98 r90 top
C21 "CL05C120JB5NNNC" 0402L 6540.73,4344.09 r270 top value=12pF
C22 "GCM1555C1H1R0CA16D" 0402L 6468.51,4395.47 r270 top value=1pF
C23 "GCM1555C1H1R0CA16D" 0402L 6395.4,4324.42 r180 top value=1pF
C24 "CL03A105MO3NRNH" FP-CL03A105MO3NRNH_0201-IPC_C 6142.33,4003.46 r180 top
C25 "GRM033R6YA104KE14D" "FP-GRM033R6YA104KE14D_0201 (0603 Metric)-IPC_C" 6156.95,4250.28 r180 top
C26 "GRM033R6YA104KE14D" "FP-GRM033R6YA104KE14D_0201 (0603 Metric)-IPC_C" 6142.18,4042.21 r180 top
C27 "GRM033R6YA104KE14D" "FP-GRM033R6YA104KE14D_0201 (0603 Metric)-IPC_C" 6559.18,4128.46 r0 top
C28 "CL05A226MQ5N6J8" FP-CL05A226MQ5N6J8_0402-IPC_C 6495.93,3931.35 r270 top
C29 "CL05A226MQ5N6J8" FP-CL05A226MQ5N6J8_0402-IPC_C 6470.18,4142.46 r180 bottom
C30 "LMK063BJ224MP-F" 0201_033L 3107,4029 r180 top value=0.22uF
C31 "TMK063CG391JT-F" "FP-TMK063CG391JT-F_0201 (0603 Metric)-IPC_C" 2861.78,4197.4 r270 top
C32 "TMK063CG391JT-F" "FP-TMK063CG391JT-F_0201 (0603 Metric)-IPC_C" 2862.17,4075.45 r90 top
C33 "TMK063CG391JT-F" "FP-TMK063CG391JT-F_0201 (0603 Metric)-IPC_C" 3352.15,4197.4 r270 top
C34 "TMK063CG391JT-F" "FP-TMK063CG391JT-F_0201 (0603 Metric)-IPC_C" 3352.48,4074.03 r90 top
C35 "GRM033R6YA104KE14D" "FP-GRM033R6YA104KE14D_0201 (0603 Metric)-IPC_C" 6471.35,4181.25 r180 bottom
C36 "GRM033R6YA104KE14D" "FP-GRM033R6YA104KE14D_0201 (0603 Metric)-IPC_C" 6518.25,4219.38 r0 top
C37 "GRM033R6YA104KE14D" "FP-GRM033R6YA104KE14D_0201 (0603 Metric)-IPC_C" 6287.19,4411.08 r180 top
C38 "250R05L120JV4T" FP-250R05L120JV4T_0201-IPC_C 5245.41,3795.56 r180 bottom
C39 "250R05L120JV4T" FP-250R05L120JV4T_0201-IPC_C 5291.16,3795.56 r0 bottom
C40 "GRM033R6YA104KE14D" "FP-GRM033R6YA104KE14D_0201 (0603 Metric)-IPC_C" 4961.7,3946.07 r0 top
C41 "GCM1555C1H1R0CA16D" 0402L 6487.09,4570.15 r270 top value=1pF
C42 "CL05A106MP5NUNC" 0402_070 6821.81,4040 r90 top value=10uF
C43 "GRM033R6YA104KE14D" "FP-GRM033R6YA104KE14D_0201 (0603 Metric)-IPC_C" 5891.78,4292.07 r0 top
C44 "CGA4J1X7T0J226M125AC" FP-CGA4J1X7T0J226M125AC_0805-MFG 2816.19,4201.22 r270 top value=22µF
C45 "CGA4J1X7T0J226M125AC" FP-CGA4J1X7T0J226M125AC_0805-MFG 2751.54,3937.35 r270 top value=22µF
C46 "CGA4J1X7T0J226M125AC" FP-CGA4J1X7T0J226M125AC_0805-MFG 3394.08,4214.97 r270 top value=22µF
C47 "CGA4J1X7T0J226M125AC" FP-CGA4J1X7T0J226M125AC_0805-MFG 3311.68,3920.88 r270 top value=22µF
C50 "CL05A106MP5NUNC" 0402_070 2981.75,4173.11 r270 top value=10uF
C51 "CL05A106MP5NUNC" 0402_070 2981.75,4110.11 r90 top value=10uF
C52 "CL05A106MP5NUNC" 0402_070 3232.25,4110.11 r90 top value=10uF
C53 "CL05A106MP5NUNC" 0402_070 3232.25,4173.11 r270 top value=10uF
C55 "CL05A106MP5NUNC" 0402_070 4115.16,4356.5 r90 bottom value=10uF
C56 "LMK063BJ224MP-F" 0201_033L 4166.37,4378.24 r0 bottom value=0.22uF
C57 "LMK063BJ224MP-F" 0201_033L 4168.42,4409.4 r0 bottom value=0.22uF
C58 "LMK063BJ224MP-F" 0201_033L 4125.06,4410.16 r180 bottom value=0.22uF
C59 "CL05A106MP5NUNC" 0402_070 4128.3,3985.94 r0 bottom value=10uF
C60 "LMK063BJ224MP-F" 0201_033L 4378.33,3871.66 r270 top value=0.22uF
C61 "LMK063BJ224MP-F" 0201_033L 4270.98,4185.3 r180 bottom value=0.22uF
C62 "CL05A106MP5NUNC" 0402_070 3907,4128 r0 bottom value=10uF
C63 "LMK063BJ224MP-F" 0201_033L 3737.19,4226.49 r90 top value=0.22uF
C64 "LMK063BJ224MP-F" 0201_033L 3907,4159 r0 bottom value=0.22uF
C65 "CL05A106MP5NUNC" 0402_070 3911,4188 r0 bottom value=10uF
C66 "LMK063BJ224MP-F" 0201_033L 3908.02,4218 r0 bottom value=0.22uF
C67 "LMK063BJ224MP-F" 0201_033L 3848,4327 r90 bottom value=0.22uF
C68 "LMK063BJ224MP-F" 0201_033L 3884.37,4409.24 r0 bottom value=0.22uF
C69 "GRM033R61C473KE84D" 0201_033L 3734.67,4322.98 r270 top value=0.047uF
C70 "CL05A106MP5NUNC" 0402_070 3891,4337 r180 bottom value=10uF
C71 "GRM0335C1H4R7BA01D" 0201_033L 3722.86,4065.25 r270 top value=4.7pF
C72 "GRM033R6YA104KE14D" "FP-GRM033R6YA104KE14D_0201 (0603 Metric)-IPC_C" 4853.37,4217.48 r270 top
C73 "CL05A106MP5NUNC" 0402_070 3897,4303 r180 bottom value=10uF
C74 "CL03A225MQ3CRNC" 0201L 3945.46,4346.38 r180 bottom value=2.2uF
C75 "LMK063BJ224MP-F" 0201_033L 3945.46,4409.24 r180 bottom value=0.22uF
C76 "LMK063BJ224MP-F" 0201_033L 3945.46,4377.91 r180 bottom value=0.22uF
C78 "CL05A106MP5NUNC" 0402_070 4038.9,4317.13 r180 bottom value=10uF
C79 "CL03A225MQ3CRNC" 0201L 4071.88,4346.34 r0 bottom value=2.2uF
C80 "LMK063BJ224MP-F" 0201_033L 4073.37,4377.75 r0 bottom value=0.22uF
C81 "LMK063BJ224MP-F" 0201_033L 4071.88,4409.36 r0 bottom value=0.22uF
C82 "CL05A106MP5NUNC" 0402_070 4001.02,4277.32 r0 bottom value=10uF
C83 "CL03A225MQ3CRNC" 0201L 4008.9,4346.15 r0 bottom value=2.2uF
C84 "LMK063BJ224MP-F" 0201_033L 4009.24,4377.83 r0 bottom value=0.22uF
C85 "LMK063BJ224MP-F" 0201_033L 4009.24,4409.33 r0 bottom value=0.22uF
C86 "GRM033R6YA104KE14D" "FP-GRM033R6YA104KE14D_0201 (0603 Metric)-IPC_C" 6422.23,3935.32 r0 bottom
C87 "LMK063BJ224MP-F" 0201_033L 4019.98,3861.38 r0 bottom value=0.22uF
C88 "LMK063BJ224MP-F" 0201_033L 4394.91,4124.76 r0 top value=0.22uF
C89 "CGB2A1X6S0J105K033BC" 0402L 3717.5,4135.45 r180 top value=1uF
C90 "CGB2A1X6S0J105K033BC" 0402L 3717.37,4182.85 r180 top value=1uF
C91 "GRM033R6YA104KE14D" "FP-GRM033R6YA104KE14D_0201 (0603 Metric)-IPC_C" 4292.99,4035.17 r180 bottom
C92 "GRM033R6YA104KE14D" "FP-GRM033R6YA104KE14D_0201 (0603 Metric)-IPC_C" 4065.74,3883.1 r90 bottom
C93 "CL05C120JB5NNNC" 0402L 6717.79,4589.83 r180 top value=12pF
C94 "LMK063BJ224MP-F" 0201_033L 4293.19,3964.68 r180 bottom value=0.22uF
C95 "LMK063BJ224MP-F" 0201_033L 3922.37,3891.76 r90 bottom value=0.22uF
C96 "LMK063BJ224MP-F" 0201_033L 4388.37,4235.76 r90 top value=0.22uF
C97 "LMK063BJ224MP-F" 0201_033L 3779.79,4050.2 r90 bottom value=0.22uF
C98 "LMK063BJ224MP-F" 0201_033L 4388.37,4297.76 r270 top value=0.22uF
C99 "GJM1555C1H1R8BB01D" 0402L 6840.79,4589.83 r180 top value=1.8pF
C100 "CL03A105MO3NRNH" FP-CL03A105MO3NRNH_0201-IPC_C 3741.24,3861.69 r0 bottom
C101 "GRM033R6YA104KE14D" "FP-GRM033R6YA104KE14D_0201 (0603 Metric)-IPC_C" 3741,3881.17 r0 bottom
C102 "CL03A225MQ3CRNC" 0201L 4393.22,4090.26 r0 top value=2.2uF
C103 "CL03A225MQ3CRNC" 0201L 4291.98,4058.8 r180 bottom value=2.2uF
C104 "GJM1555C1H1R8BB01D" 0402L 6962.22,4570.15 r270 top value=1.8pF
C105 "GRM033R6YA104KE14D" "FP-GRM033R6YA104KE14D_0201 (0603 Metric)-IPC_C" 6003.64,4429.32 r90 top
C106 "GRM155R71H472KA01D" 0402L 6042.33,4472.32 r90 top value=4700pF
C107 "GRM033R6YA104KE14D" "FP-GRM033R6YA104KE14D_0201 (0603 Metric)-IPC_C" 6735.03,4433.22 r90 top
C108 "GRM033R6YA104KE14D" "FP-GRM033R6YA104KE14D_0201 (0603 Metric)-IPC_C" 6709.78,3866.01 r270 top
C109 "GRM033R6YA104KE14D" "FP-GRM033R6YA104KE14D_0201 (0603 Metric)-IPC_C" 6877.41,3768.9 r0 top
C110 "GRM155R71H472KA01D" 0402L 6951.81,3773.61 r90 top value=4700pF
C111 "CGA4J1X7T0J226M125AC" FP-CGA4J1X7T0J226M125AC_0805-MFG 3322.6,4362.32 r90 top value=22µF
C112 "CGA4J1X7T0J226M125AC" FP-CGA4J1X7T0J226M125AC_0805-MFG 2818.89,4074.44 r90 top value=22µF
C113 "CGA4J1X7T0J226M125AC" FP-CGA4J1X7T0J226M125AC_0805-MFG 3244.4,4362.32 r90 top value=22µF
C114 "GRM033R6YA104KE14D" "FP-GRM033R6YA104KE14D_0201 (0603 Metric)-IPC_C" 6174.57,3747.34 r180 bottom
C115 "CL03A105MO3NRNH" FP-CL03A105MO3NRNH_0201-IPC_C 5764.72,3872.2 r0 top
C116 "CL03A105MO3NRNH" FP-CL03A105MO3NRNH_0201-IPC_C 5764.72,3843.74 r0 top
C117 "GRM033R6YA104KE14D" "FP-GRM033R6YA104KE14D_0201 (0603 Metric)-IPC_C" 5322,4534 r0 bottom
C118 "GRM033R6YA104KE14D" "FP-GRM033R6YA104KE14D_0201 (0603 Metric)-IPC_C" 6272.5,3733.87 r270 bottom
C119 "GRM033R6YA104KE14D" "FP-GRM033R6YA104KE14D_0201 (0603 Metric)-IPC_C" 6308.91,3909.21 r90 bottom
C120 "GRM033R6YA104KE14D" "FP-GRM033R6YA104KE14D_0201 (0603 Metric)-IPC_C" 4784.37,4437.46 r90 top
C121 "CGA4J1X7T0J226M125AC" FP-CGA4J1X7T0J226M125AC_0805-MFG 3396.69,4076.02 r90 top value=22µF
C122 "CL05A106MP5NUNC" 0402_070 6771.81,4040 r270 top value=10uF
C123 "GRM033R6YA104KE14D" "FP-GRM033R6YA104KE14D_0201 (0603 Metric)-IPC_C" 5432.91,4016.37 r270 bottom
C124 "GCM21BR71A106KE22L" 0805_HV 3091.88,4372.69 r270 bottom value=10uF
C125 "CL03A103KA3NNNC" FP-CL03A103KA3NNNC_0201-IPC_C 5270.83,4102.9 r0 bottom locked
C126 "GRM033R6YA104KE14D" "FP-GRM033R6YA104KE14D_0201 (0603 Metric)-IPC_C" 3679.93,4262.91 r0 top
C127 "GRM033R6YA104KE14D" "FP-GRM033R6YA104KE14D_0201 (0603 Metric)-IPC_C" 6653.18,3936.75 r180 bottom
C128 "GRM033R6YA104KE14D" "FP-GRM033R6YA104KE14D_0201 (0603 Metric)-IPC_C" 6643.28,3766.12 r180 bottom
C129 "CL03A105MO3NRNH" FP-CL03A105MO3NRNH_0201-IPC_C 6719.58,3813.74 r270 bottom
C130 "GRM033R6YA104KE14D" "FP-GRM033R6YA104KE14D_0201 (0603 Metric)-IPC_C" 4251.69,4228 r180 bottom
C131 "CGA4J1X7T0J226M125AC" FP-CGA4J1X7T0J226M125AC_0805-MFG 3462.45,4216.65 r270 top value=22µF
C132 "GCM21BR71A106KE22L" 0805_HV 3541.84,4216.94 r270 top value=10uF
C133 "CGA4J1X7T0J226M125AC" FP-CGA4J1X7T0J226M125AC_0805-MFG 2979.21,3912.58 r90 top value=22µF
C134 "GCM21BR71A106KE22L" 0805_HV 2883.61,3922.66 r90 bottom value=10uF
C135 "CGA4J1X7T0J226M125AC" FP-CGA4J1X7T0J226M125AC_0805-MFG 3466.11,4077.11 r90 top value=22µF
C136 "GCM21BR71A106KE22L" 0805_HV 3428.48,3894.97 r180 top value=10uF
C137 "CGA4J1X7T0J226M125AC" FP-CGA4J1X7T0J226M125AC_0805-MFG 3074.32,4359.33 r270 top value=22µF
C138 "CGA4J1X7T0J226M125AC" FP-CGA4J1X7T0J226M125AC_0805-MFG 3559.23,3925.63 r0 top value=22µF
C139 "CGA4J1X7T0J226M125AC" FP-CGA4J1X7T0J226M125AC_0805-MFG 2997.27,4360.78 r270 top value=22µF
C140 "CGA4J1X7T0J226M125AC" FP-CGA4J1X7T0J226M125AC_0805-MFG 3544.88,4403.6 r0 top value=22µF
C141 "CGA4J1X7T0J226M125AC" FP-CGA4J1X7T0J226M125AC_0805-MFG 2905,3911.44 r90 top value=22µF
D1 "NSR20F30NXT5G" DSN2_0603 2804.54,4211.99 r270 bottom value=30V
D2 "NSR20F30NXT5G" DSN2_0603 4603.84,3756.88 r0 top locked value=30V
Designator1 "Comment" MHNP_M2_PANHEAD_PHILLIPS 2684.58,4830.46 r0 top
Designator1_2 "Comment" MHNP_M2_PANHEAD_PHILLIPS 2684.58,3467.85 r0 bottom
Designator2 "BRAKE_WAY_HOLES1X2" BRAKE_WAY_HOLES1X2 3353.11,4495.01 r180 top
Designator2_1 "BRAKE_WAY_HOLES1X2" BRAKE_WAY_HOLES1X2 3353.11,3788.2 r180 bottom
Designator3 "BRAKE_WAY_HOLES1X2" BRAKE_WAY_HOLES1X2 3848.11,4495.01 r180 top
Designator3_1 "BRAKE_WAY_HOLES1X2" BRAKE_WAY_HOLES1X2 3848.11,3788.2 r180 bottom
Designator4 "BRAKE_WAY_HOLES1X2" BRAKE_WAY_HOLES1X2 4723.45,4688.12 r180 top
Designator4_1 "BRAKE_WAY_HOLES1X2" BRAKE_WAY_HOLES1X2 4723.13,3606.99 r180 bottom
Designator5 "BRAKE_WAY_HOLES1X2" BRAKE_WAY_HOLES1X2 6701.12,4687.21 r180 top
Designator5_1 "BRAKE_WAY_HOLES1X2" BRAKE_WAY_HOLES1X2 6700.8,3607.9 r180 bottom
Designator6 "Comment" MHNP_M2_PANHEAD_PHILLIPS 7012.34,4830.46 r0 top
Designator7 "Comment" MHNP_M2_PANHEAD_PHILLIPS 7012.03,3464.65 r0 top
Designator10 "BRAKE_WAY_HOLES1X2" BRAKE_WAY_HOLES1X2 2846.89,4495.01 r180 top
Designator11 "BRAKE_WAY_HOLES1X2" BRAKE_WAY_HOLES1X2 2846.89,3788.2 r180 bottom
Designator22_1 "Comment" MHNP_2-5 6425,3754.84 r0 bottom
Designator23 "Comment" MHNP_2-5 5014.62,3754.06 r0 bottom
FID1 "Fiducial" Fiducial6.4-20 2829.73,4789.08 r90 top
FID2 "Fiducial" Fiducial6.4-20 2829.73,4789.08 r90 bottom
FID3 "Fiducial" Fiducial6.4-20 2829.73,3469.51 r90 top
FID4 "Fiducial" Fiducial6.4-20 2829.73,3469.51 r90 bottom
FID5 "Fiducial" Fiducial6.4-20 6846.16,3469.51 r90 top
FID6 "Fiducial" Fiducial6.4-20 6846.16,3469.51 r90 bottom
FL2 "BLM15PD300SZ1D" 0402L 2803.8,4133.28 r90 bottom
FL3 "BLM15PD300SZ1D" 0402L 6670.79,3868.56 r90 top
FL4 "BLM15PD300SZ1D" 0402L 5641.61,4417.35 r180 bottom
FL11 "BLM15PD300SZ1D" 0402L 4674.94,3755.5 r180 top locked
FL12 "BLM15PD300SZ1D" 0402L 5955.92,4292.41 r0 top
FL14 "BLM15PD300SZ1D" 0402L 6841.81,4105.18 r180 top
FL22 "BLM15PD300SZ1D" 0402L 4843.47,3842.73 r270 top locked
J1 "105017-0001" CONN_105017-0001 2694.51,4164.78 r90 bottom
J2 "QSH-030-01-L-D-A" Samtec_QSH-030-01-X-D-A 4733.36,4144.5 r0 bottom locked
J3 "M50-3930442" FP-M50-3930442_HDR4-RECOMMENDED_LAND_PATTERN 5065.29,4621.12 r0 bottom
J4 "51441-1093" FP-51441-1093_CONN_SMD_FFC-0 4585.45,4173.34 r270 top locked
J5 "105017-0001" CONN_105017-0001 6998.66,4155.73 r90 top
J6 "51441-1093" FP-51441-1093_CONN_SMD_FFC-0 5711.91,3740.17 r0 top
J7 "GRPB052MWCN-RC" FP-GRPB052MWCN-RC_HDR10-MFG 6233.84,4610.83 r180 top
J8 "M50-3930342" FP-M50-3930342_HDR3-MFG 5923.44,4618.25 r180 top
J9 "U.FL-R-SMT-1(01)" CONN_UFL-R-SMT-1 5264.12,4518.36 r90 top
J10 "M50-3930342" FP-M50-3930342_HDR3-MFG 7094.18,3800 r90 top
J11 "QSH-030-01-L-D-A" Samtec_QSH-030-01-X-D-A 5895.12,4104.5 r180 bottom
L1 "LQG15HS2N4S02D" IND_LQG15H 6487.22,4324.41 r0 top value=2.4nH
L2 "MCKK2012TR47M" "FP-MCKK2012TR47M_0805 (2012 Metric)-IPC_C" 2926.51,4230.34 r270 top
L3 "MCKK2012TR47M" "FP-MCKK2012TR47M_0805 (2012 Metric)-IPC_C" 2927.23,4046.77 r90 top
L4 "MCKK2012TR47M" "FP-MCKK2012TR47M_0805 (2012 Metric)-IPC_C" 3286.89,4231.94 r270 top
L5 "MCKK2012TR47M" "FP-MCKK2012TR47M_0805 (2012 Metric)-IPC_C" 3288.17,4048.9 r90 top
L6 "LQG15HS2N4S02D" IND_LQG15H 6415.18,4396.46 r90 top value=2.4nH
L7 "MLZ2012N6R8LT000" 0805_HV 6491.96,4040.83 r90 bottom value=6.8uH
L8 "BLM18HE152SN1D" 0603L 6552.57,3919.1 r90 top value="1500 ohm"
L9 "LQG15HS2N0S02D" IND_LQG15H 6441.85,4524.72 r90 top value=2nH
L10 "LQG15HS2N0S02D" IND_LQG15H 6597.79,4589.83 r0 top value=2nH
L11 "BLM18KG121TH1D" 0603 3426.56,3974.36 r0 top value="120 ohm"
L12 "BLM18KG121TH1D" 0603 3147.81,4365.66 r90 top value="120 ohm"
L13 "BLM18KG121TH1D" 0603 2825,3953.79 r270 top value="120 ohm"
L14 "BLM18KG121TH1D" 0603 3427.09,4316.3 r0 top value="120 ohm"
L15 "BLM21PG221SN1D" 0805L 3421.44,4384.34 r0 top value="220 ohm"
LD1 "APHHS1005CGCK" APHHS1005_Green 2696.65,4188.5 r0 top value=Green
LD2 "APHHS1005CGCK" APHHS1005_Green 4607.12,4561.07 r180 top locked value=Green
LD3 "APHHS1005CGCK" APHHS1005_Green 4758.14,4558.15 r0 top value=Green
LD4 "APHHS1005CGCK" APHHS1005_Green 3600,4117.07 r0 top value=Green
LD5 "APHHS1005CGCK" APHHS1005_Green 4958.55,4422.56 r0 top value=Green
LD6 "APHHS1005CGCK" APHHS1005_Green 6248.18,4393.36 r90 top value=Green
Q1 "BSS123-7-F" FP-BSS123-7-F_SOT23-IPC_C 5205.08,4356.86 r90 top
R1 "RR0306P-103-D" FP-RR0306P-103-D_0201-IPC_C#1 5444.85,4116.98 r180 bottom
R2 "RC0201JR-070RL" "FP-RC0201JR-070RL_0201 (0603 Metric)-MFG" 4295.7,4110.3 r270 bottom
R3 "RR0306P-103-D" FP-RR0306P-103-D_0201-IPC_C#1 3793.63,3912.76 r180 bottom
R4 "CRCW0201100KFKED" 0201L 3717.54,4429.01 r180 top value=100k
R5 "CRCW0201100KFKED" 0201L 4378.13,4374.27 r270 top value=100k
R6 "CRCW020133R2FNED" 0201L 3706.27,4022.49 r270 bottom value=33.2
R7 "RR0306P-103-D" FP-RR0306P-103-D_0201-IPC_C#1 3840.93,3972.06 r270 bottom
R8 "RR0306P-103-D" FP-RR0306P-103-D_0201-IPC_C#1 3867.48,3948.46 r270 bottom
R9 "CRCW0201100KFKED" 0201L 3835,3920.2 r270 bottom value=100k
R10 "AC0201FR-0720RL" FP-AC0201FR-0720RL_0201-IPC_C 4917.01,3921 r180 bottom
R11 "AC0201FR-0720RL" FP-AC0201FR-0720RL_0201-IPC_C 4950.01,3937.94 r180 bottom
R12 "RC0201JR-070RL" "FP-RC0201JR-070RL_0201 (0603 Metric)-MFG" 4898.97,4582.07 r0 bottom
R13 "RC0201JR-07220RL" 0201L 4636.42,4516.76 r180 top locked value=220
R14 "RC0201JR-070RL" "FP-RC0201JR-070RL_0201 (0603 Metric)-MFG" 4886,4506.26 r90 top
R15 "RC0201JR-07220RL" 0201L 3663,4121.49 r90 top value=220
R16 "RC0201FR-077K87L" 0201L 5566.39,4484.46 r180 top value=7.87k
R17 "RC0201JR-07220RL" 0201L 6248.18,4328.17 r90 top value=220
R18 "RR0306P-103-D" FP-RR0306P-103-D_0201-IPC_C#1 5362.78,4021.8 r270 bottom
R19 "RR0306P-103-D" FP-RR0306P-103-D_0201-IPC_C#1 3579.99,4328.04 r90 top
R20 "RR0306P-103-D" FP-RR0306P-103-D_0201-IPC_C#1 6584.18,3988.94 r180 bottom
R21 "RR0306P-103-D" FP-RR0306P-103-D_0201-IPC_C#1 4318.97,4310.76 r0 bottom
R22 "RR0306P-103-D" FP-RR0306P-103-D_0201-IPC_C#1 4318.97,4288.76 r0 bottom
R23 "RR0306P-103-D" FP-RR0306P-103-D_0201-IPC_C#1 4301.24,4249.29 r0 bottom
R24 "CRCW0402200RFKEDHP" FP-CRCW0402200RFKEDHP_0402-IPC_C 6583.18,3937.46 r180 bottom
R25 "RC0201FR-074K99L" 0201L 3065.02,4017.98 r270 top value=4.99k
R26 "RC0201FR-074K99L" 0201L 3146.72,4016.87 r270 top value=4.99k
R27 "RC0201JR-07510RL" 0201L 6606.39,3752.54 r90 bottom value=510
R28 "RC0201JR-070RL" "FP-RC0201JR-070RL_0201 (0603 Metric)-MFG" 3062.78,4258.34 r270 top
R29 "CRCW0201100KFKED" 0201L 6584.18,3965.94 r180 bottom value=100k
R30 "RC0201JR-070RL" "FP-RC0201JR-070RL_0201 (0603 Metric)-MFG" 5226,4430 r0 bottom
R31 "RC0201JR-070RL" "FP-RC0201JR-070RL_0201 (0603 Metric)-MFG" 5010.88,4011.31 r0 bottom
R32 "RC0201JR-070RL" "FP-RC0201JR-070RL_0201 (0603 Metric)-MFG" 3094.52,4264.13 r270 top
R33 "RC0201FR-074K99L" 0201L 3175.06,4016.87 r270 top value=4.99k
R34 "RC0201FR-074K99L" 0201L 3001.77,4272.69 r180 top value=4.99k
R35 "RR0306P-103-D" FP-RR0306P-103-D_0201-IPC_C#1 3034.52,4017.52 r270 top
R36 "RR0306P-103-D" FP-RR0306P-103-D_0201-IPC_C#1 3166.73,4249.57 r0 top
R37 "CRCW0201100KFKED" 0201L 5009.23,3983.33 r180 bottom value=100k
R38 "RC0201FR-074K99L" 0201L 5272,4240 r90 bottom value=4.99k
R39 "RC0201JR-07510RL" 0201L 2665.67,4224.06 r0 top value=510
R40 "RC0201FR-074K99L" 0201L 3660.79,4145.37 r0 bottom value=4.99k
R41 "RC0201JR-070RL" "FP-RC0201JR-070RL_0201 (0603 Metric)-MFG" 3825.31,4374.62 r90 bottom
R42 "RC0201JR-07220RL" 0201L 4799.25,4494.23 r270 top locked value=220
R43 "RR0306P-103-D" FP-RR0306P-103-D_0201-IPC_C#1 3630.7,3875.43 r0 bottom
R44 "RR0306P-103-D" FP-RR0306P-103-D_0201-IPC_C#1 3619.37,4059.85 r0 bottom
R45 "RR0306P-103-D" FP-RR0306P-103-D_0201-IPC_C#1 3809.22,3978.91 r0 bottom
R46 "CRCW020133R2FNED" 0201L 3595.37,3913.81 r90 bottom value=33.2
R47 "CRCW020133R2FNED" 0201L 3734.37,4022.49 r270 bottom value=33.2
R48 "CRCW020133R2FNED" 0201L 3608.37,4021.09 r270 bottom value=33.2
R49 "CRCW020133R2FNED" 0201L 3771.3,3947.76 r270 bottom value=33.2
R50 "RC0201JR-071KL" 0201L 2834.18,4320.16 r180 top value=1.0k
R51 "RC0201JR-070RL" "FP-RC0201JR-070RL_0201 (0603 Metric)-MFG" 5232,4241.8 r270 bottom
R52 "RC0201FR-071K96L" 0201L 2861.97,4366.38 r270 top value=1.96k
R53 "RC0402FR-073R83L" "FP-RC0402FR-073R83L_0402 (1005 Metric)-IPC_C" 2884.16,4203.5 r270 top
R54 "RC0402FR-073R83L" "FP-RC0402FR-073R83L_0402 (1005 Metric)-IPC_C" 2883.09,4075.35 r90 top
R55 "RC0402FR-073R83L" "FP-RC0402FR-073R83L_0402 (1005 Metric)-IPC_C" 3329.41,4204.49 r270 top
R56 "RC0402FR-073R83L" "FP-RC0402FR-073R83L_0402 (1005 Metric)-IPC_C" 3331.14,4076.1 r90 top
R57 "RC0201JR-070RL" "FP-RC0201JR-070RL_0201 (0603 Metric)-MFG" 5198,4147.8 r270 bottom
R58 "RC0201JR-070RL" "FP-RC0201JR-070RL_0201 (0603 Metric)-MFG" 5008.99,4046.94 r180 bottom
R59 "RR0306P-103-D" FP-RR0306P-103-D_0201-IPC_C#1 4301.24,4224.76 r0 bottom
R60 "RC0201JR-070RL" "FP-RC0201JR-070RL_0201 (0603 Metric)-MFG" 3846.82,4374.62 r90 bottom
R61 "RC0201JR-070RL" "FP-RC0201JR-070RL_0201 (0603 Metric)-MFG" 3906.47,3996.54 r180 bottom
R62 "RC0201JR-070RL" "FP-RC0201JR-070RL_0201 (0603 Metric)-MFG" 3901.53,3973.85 r180 bottom
R64 "RC0201FR-074K99L" 0201L 3715.38,4103.78 r90 bottom value=4.99k
R65 "RR0306P-103-D" FP-RR0306P-103-D_0201-IPC_C#1 3708.05,4143.04 r0 bottom
R66 "RC0201JR-070RL" "FP-RC0201JR-070RL_0201 (0603 Metric)-IPC_C" 4952.38,4360.97 r0 top
R67 "RC0201JR-070RL" "FP-RC0201JR-070RL_0201 (0603 Metric)-MFG" 5513.34,3938.91 r0 bottom
R68 "RC0201JR-070RL" "FP-RC0201JR-070RL_0201 (0603 Metric)-MFG" 5601.88,3937.06 r180 bottom
R69 "RC0201FR-074K99L" 0201L 5505.11,3737.11 r180 bottom value=4.99k
R70 "RC0201JR-070RL" "FP-RC0201JR-070RL_0201 (0603 Metric)-MFG" 5434,3877.69 r0 bottom
R71 "RC0201JR-070RL" "FP-RC0201JR-070RL_0201 (0603 Metric)-MFG" 5396.26,3801.26 r0 bottom
R72 "RC0201JR-070RL" "FP-RC0201JR-070RL_0201 (0603 METRIC)-IPC_C" 5422.76,3927.24 r270 bottom
R73 "RC0201JR-070RL" "FP-RC0201JR-070RL_0201 (0603 METRIC)-IPC_C" 5458.86,3908 r180 bottom
R74 "RC0201JR-070RL" "FP-RC0201JR-070RL_0201 (0603 METRIC)-IPC_C" 4961.7,3922.44 r180 top
R75 "RC0201JR-071KL" 0201L 3869.6,3903.22 r270 bottom value=1.0k
R76 "RC0201JR-070RL" "FP-RC0201JR-070RL_0201 (0603 METRIC)-IPC_C" 6210.78,3903.45 r90 bottom
R77 "RR0306P-103-D" FP-RR0306P-103-D_0201-IPC_C#1 5185.3,4021 r270 bottom
R78 "RR0306P-103-D" FP-RR0306P-103-D_0201-IPC_C#1 5155,3984 r0 bottom
R79 "ERJ-1GNF4701C" FP-ERJ-1GNF4701C_0201-IPC_C 6300.48,3846.46 r90 bottom
R80 "RR0306P-103-D" FP-RR0306P-103-D_0201-IPC_C#1 5155.48,3915 r0 bottom
R81 "RR0306P-103-D" FP-RR0306P-103-D_0201-IPC_C#1 5315.24,4059.87 r180 bottom
R82 "RR0306P-103-D" FP-RR0306P-103-D_0201-IPC_C#2 5279.72,4021 r270 bottom
R83 "RR0306P-103-D" FP-RR0306P-103-D_0201-IPC_C#1 4277.8,4155.3 r180 bottom
R84 "RR0306P-103-D" FP-RR0306P-103-D_0201-IPC_C#1 4119.89,3922.4 r0 bottom
R85 "RR0306P-103-D" FP-RR0306P-103-D_0201-IPC_C#1 4355.44,4224.99 r0 bottom
R86 "RC0201JR-070RL" "FP-RC0201JR-070RL_0201 (0603 METRIC)-IPC_C" 6141.03,4180.57 r0 top
R87 "RC0201JR-070RL" "FP-RC0201JR-070RL_0201 (0603 METRIC)-IPC_C" 6141.18,4202.46 r0 top
R88 "AC0201FR-0720RL" FP-AC0201FR-0720RL_0201-IPC_C 4807.4,4192.67 r270 top
R89 "CRCW0201100KFKED" 0201L 6338.19,4411.08 r0 top value=100k
R90 "RC0201JR-070RL" "FP-RC0201JR-070RL_0201 (0603 METRIC)-IPC_C" 6278.99,4249 r0 bottom
R91 "RC0201JR-070RL" "FP-RC0201JR-070RL_0201 (0603 METRIC)-IPC_C" 6421.95,3926.46 r180 top
R92 "CRCW0201100KFKED" 0201L 6583.22,3689.74 r0 bottom value=100k
R93 "RR0306P-103-D" FP-RR0306P-103-D_0201-IPC_C#1 5206.3,4021 r90 bottom
R94 "RR0306P-103-D" FP-RR0306P-103-D_0201-IPC_C#1 5398,4473.91 r0 bottom locked
R95 "RR0306P-103-D" FP-RR0306P-103-D_0201-IPC_C#1 5223.49,4457.6 r180 bottom
R96 "RR0306P-103-D" FP-RR0306P-103-D_0201-IPC_C#1 5155.48,3938 r180 bottom
R97 "RC0201JR-070RL" "FP-RC0201JR-070RL_0201 (0603 METRIC)-IPC_C" 5304.72,4020.49 r90 bottom
R98 "RR0306P-103-D" FP-RR0306P-103-D_0201-IPC_C#1 5155,3961 r180 bottom
R99 "RC0201JR-070RL" "FP-RC0201JR-070RL_0201 (0603 METRIC)-IPC_C" 5223.3,4485 r180 bottom
R100 "RC0201JR-070RL" "FP-RC0201JR-070RL_0201 (0603 METRIC)-IPC_C" 5331,4360.01 r90 bottom
R101 "RC0201JR-070RL" "FP-RC0201JR-070RL_0201 (0603 METRIC)-IPC_C" 5273.16,4534.36 r180 bottom
R102 "RC0201JR-070RL" "FP-RC0201JR-070RL_0201 (0603 METRIC)-IPC_C" 6278.99,4272.45 r0 bottom
R103 "RC0201JR-070RL" "FP-RC0201JR-070RL_0201 (0603 METRIC)-IPC_C" 4355.64,4245.1 r0 bottom
R104 "RR0306P-103-D" FP-RR0306P-103-D_0201-IPC_C#1 4961.33,3971.36 r0 top
R105 "RC0201JR-070RL" "FP-RC0201JR-070RL_0201 (0603 METRIC)-IPC_C" 4865.78,3995.57 r90 top
R106 "RC0201JR-070RL" "FP-RC0201JR-070RL_0201 (0603 METRIC)-IPC_C" 4902.35,3985.56 r0 top locked
R107 "RC0201JR-07510RL" 0201L 4951.64,4484.7 r180 top value=510
R108 "RC0201JR-07510RL" 0201L 4924,4194 r0 top value=510
R109 "RC0201JR-070RL" "FP-RC0201JR-070RL_0201 (0603 Metric)-MFG" 3732.14,4012.38 r0 top
R110 "RR0306P-103-D" FP-RR0306P-103-D_0201-IPC_C#1 6168.27,4114.75 r270 bottom
R111 "RC0201JR-07220RL" 0201L 5137.39,4116.46 r0 top value=220
R112 "RC0201JR-070RL" "FP-RC0201JR-070RL_0201 (0603 METRIC)-IPC_C" 5259.36,4367.46 r0 bottom
R113 "RC0201JR-070RL" "FP-RC0201JR-070RL_0201 (0603 METRIC)-IPC_C" 5223.3,4399 r0 bottom
R114 "CRCW040261R9FKED" 0402L 6909.57,3909.29 r270 top value=61.9
R115 "RC0201JR-070RL" "FP-RC0201JR-070RL_0201 (0603 Metric)-IPC_C" 6854.79,3961 r0 top
R116 "RC0201JR-070RL" "FP-RC0201JR-070RL_0201 (0603 Metric)-IPC_C" 6754.79,3956 r0 top
R117 "CRCW040261R9FKED" 0402L 6909.66,3823.52 r270 top value=61.9
R118 "RR0306P-103-D" FP-RR0306P-103-D_0201-IPC_C#1 6696.81,4422 r90 top
R119 "CRCW040261R9FKED" 0402L 5885.96,4492.77 r0 top value=61.9
R120 "RC0201JR-070RL" "FP-RC0201JR-070RL_0201 (0603 Metric)-IPC_C" 6802.81,4252.99 r90 top
R121 "RC0201JR-070RL" "FP-RC0201JR-070RL_0201 (0603 METRIC)-IPC_C" 6649.04,4333.23 r180 top
R122 "RR0306P-103-D" FP-RR0306P-103-D_0201-IPC_C#1 5837.64,4429.06 r270 top
R123 "RC0201JR-070RL" "FP-RC0201JR-070RL_0201 (0603 METRIC)-IPC_C" 5843.14,4359.71 r90 top
R124 "RR0306P-103-D" FP-RR0306P-103-D_0201-IPC_C#1 4864.68,4471.7 r0 top
R125 "RR0306P-103-D" FP-RR0306P-103-D_0201-IPC_C#1 5087.65,3914.04 r0 top
R126 "CRCW040261R9FKED" 0402L 5960.92,4492.48 r0 top value=61.9
R127 "RC0201JR-070RL" "FP-RC0201JR-070RL_0201 (0603 METRIC)-IPC_C" 6649.8,4310 r0 top
R128 "RC0201JR-070RL" "FP-RC0201JR-070RL_0201 (0603 METRIC)-IPC_C" 6695.72,4240.71 r180 top
R129 "RC0201JR-070RL" "FP-RC0201JR-070RL_0201 (0603 METRIC)-IPC_C" 5125.2,3925.93 r90 top
R130 "AC0201FR-0720RL" FP-AC0201FR-0720RL_0201-IPC_C 4617.95,4372.15 r270 top locked
R131 "RC0201JR-070RL" "FP-RC0201JR-070RL_0201 (0603 METRIC)-IPC_C" 6321.17,3978.41 r180 bottom
R132 "AC0201FR-0720RL" FP-AC0201FR-0720RL_0201-IPC_C 4783.74,4192.67 r270 top
R133 "AC0201FR-0720RL" FP-AC0201FR-0720RL_0201-IPC_C 4740.67,4227.63 r180 top locked
R134 "RR0306P-103-D" FP-RR0306P-103-D_0201-IPC_C#1 6900.3,3961 r0 top
R135 "AC0201FR-0720RL" FP-AC0201FR-0720RL_0201-IPC_C 4722.06,4196.8 r180 top locked
R136 "RC0201JR-070RL" "FP-RC0201JR-070RL_0201 (0603 Metric)-IPC_C" 6749.82,4241 r0 top
R137 "AC0201FR-0720RL" FP-AC0201FR-0720RL_0201-IPC_C 4649.26,3816.82 r90 top
R138 "AC0201FR-0720RL" FP-AC0201FR-0720RL_0201-IPC_C 4767.38,4284.46 r180 top
R139 "RC0201JR-070RL" "FP-RC0201JR-070RL_0201 (0603 Metric)-IPC_C" 6824.81,4252.99 r270 top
